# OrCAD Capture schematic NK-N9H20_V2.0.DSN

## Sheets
1 TOP: size A3; rev: 1.1; company: NuMaker-HMI-N9H20; note: TOP; note: NHS-55FA93 V1.0
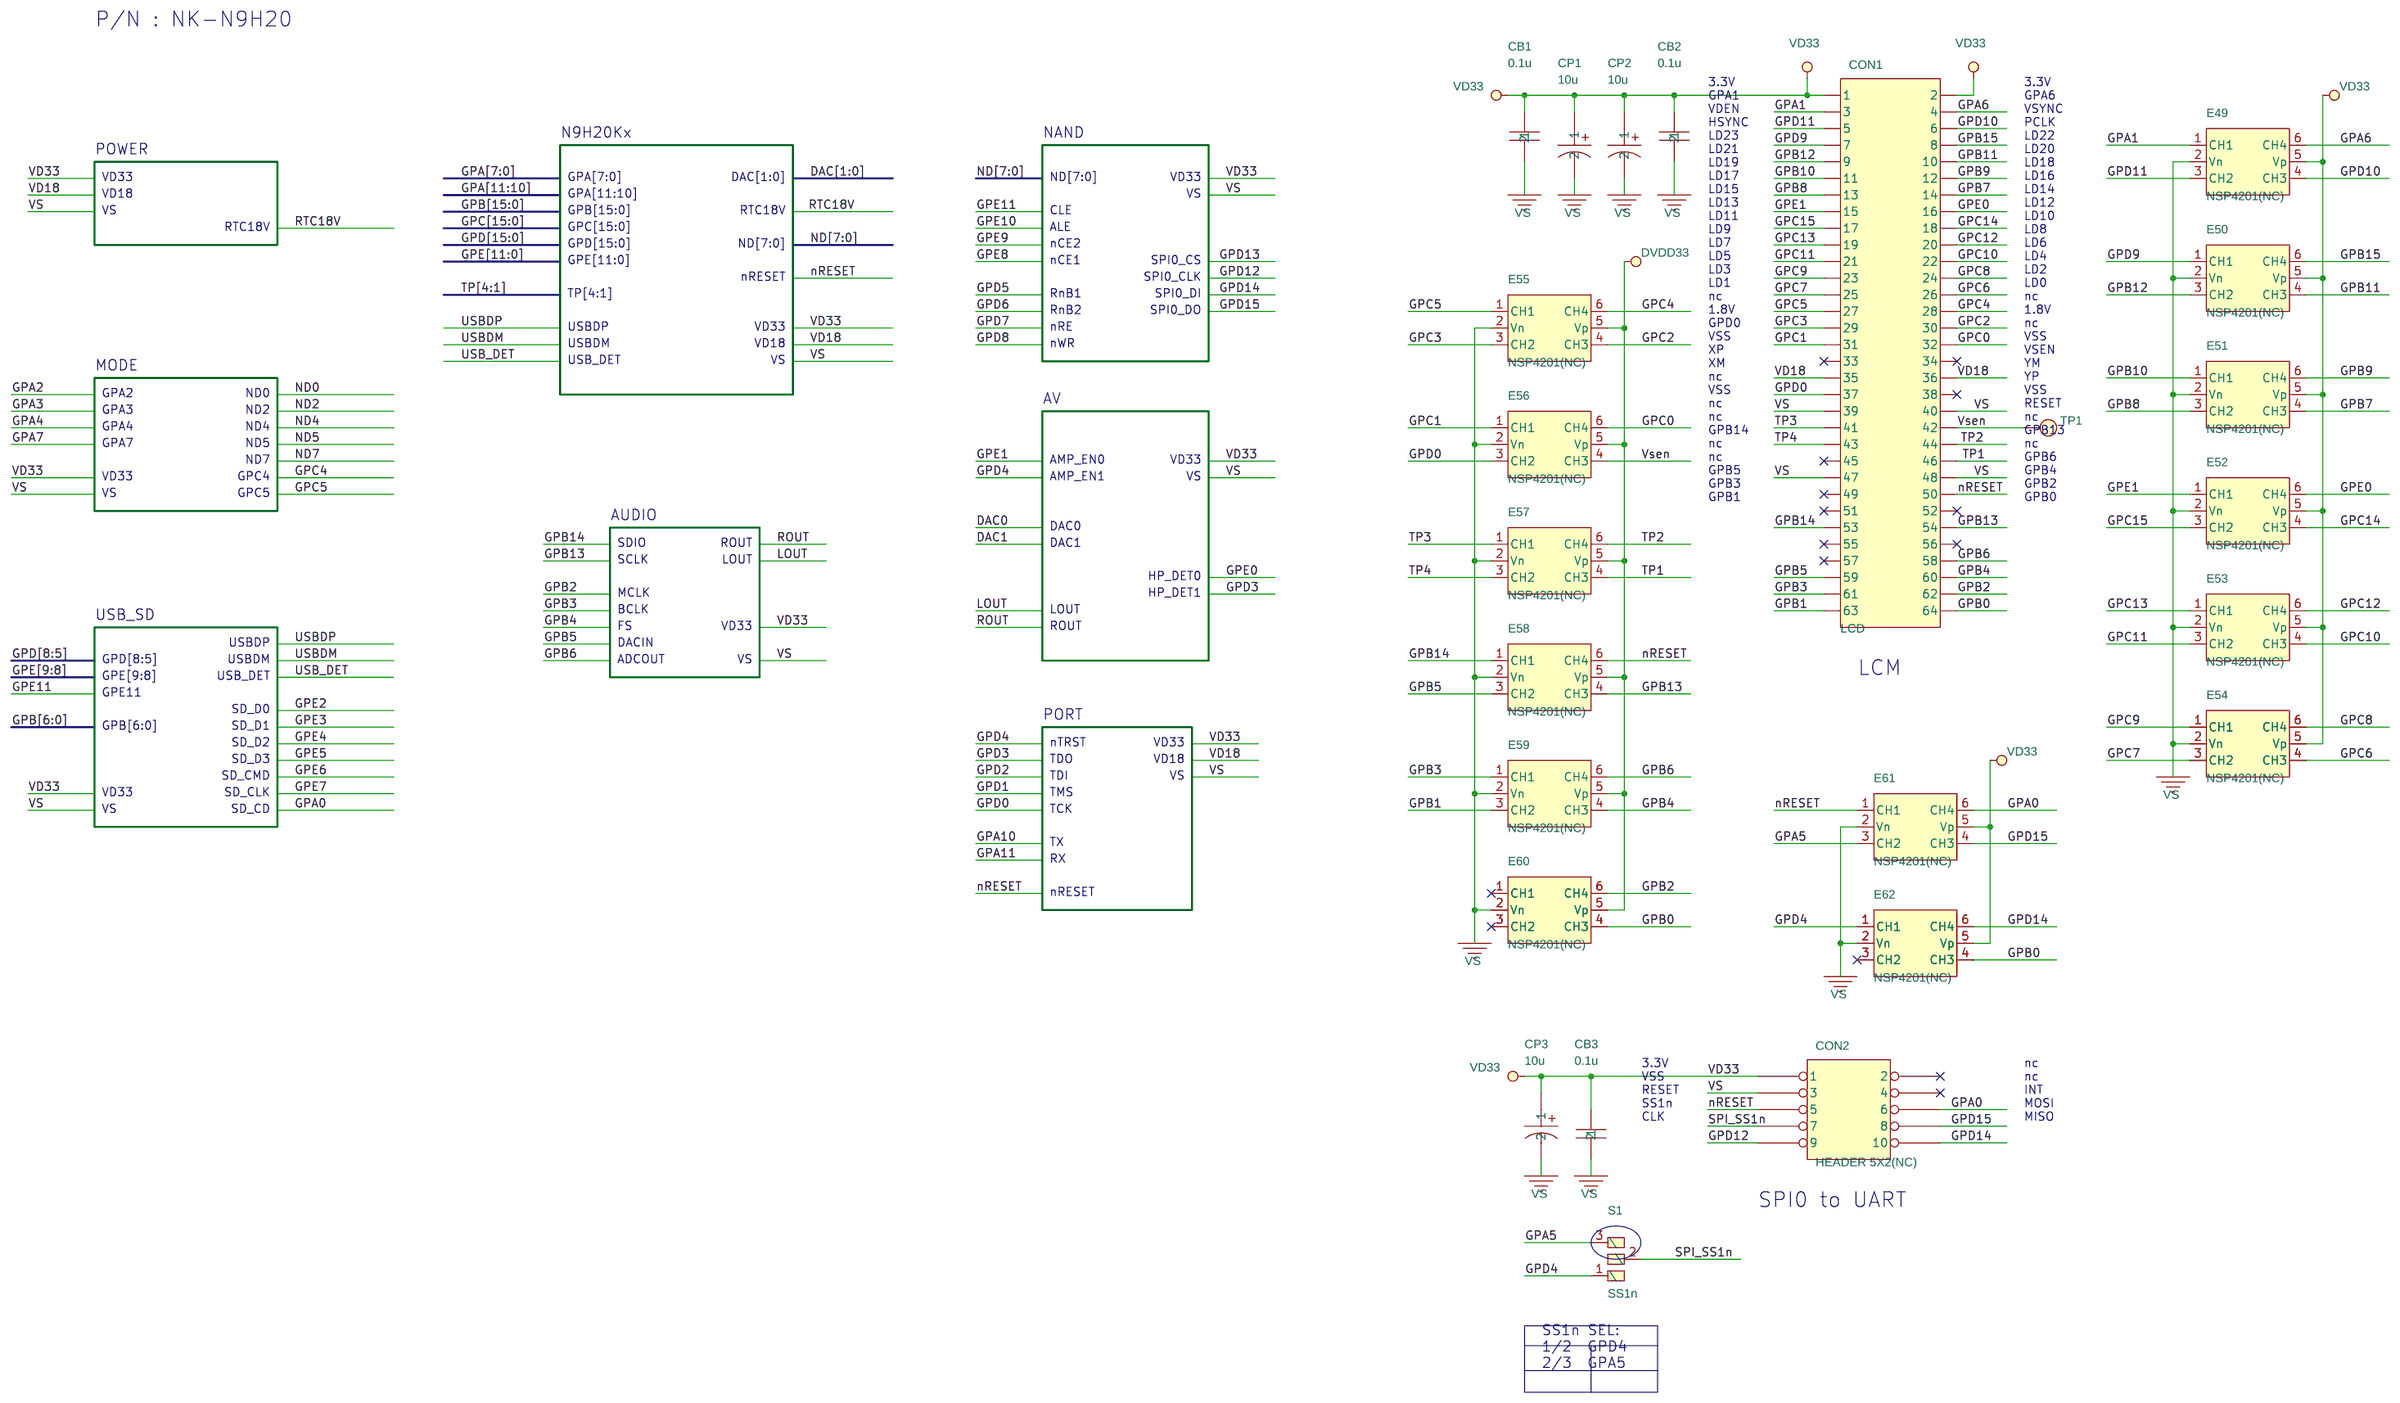
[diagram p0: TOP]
2 AV: size A4; note: AV; note: NuMaker-HMI-N9H20; block AV
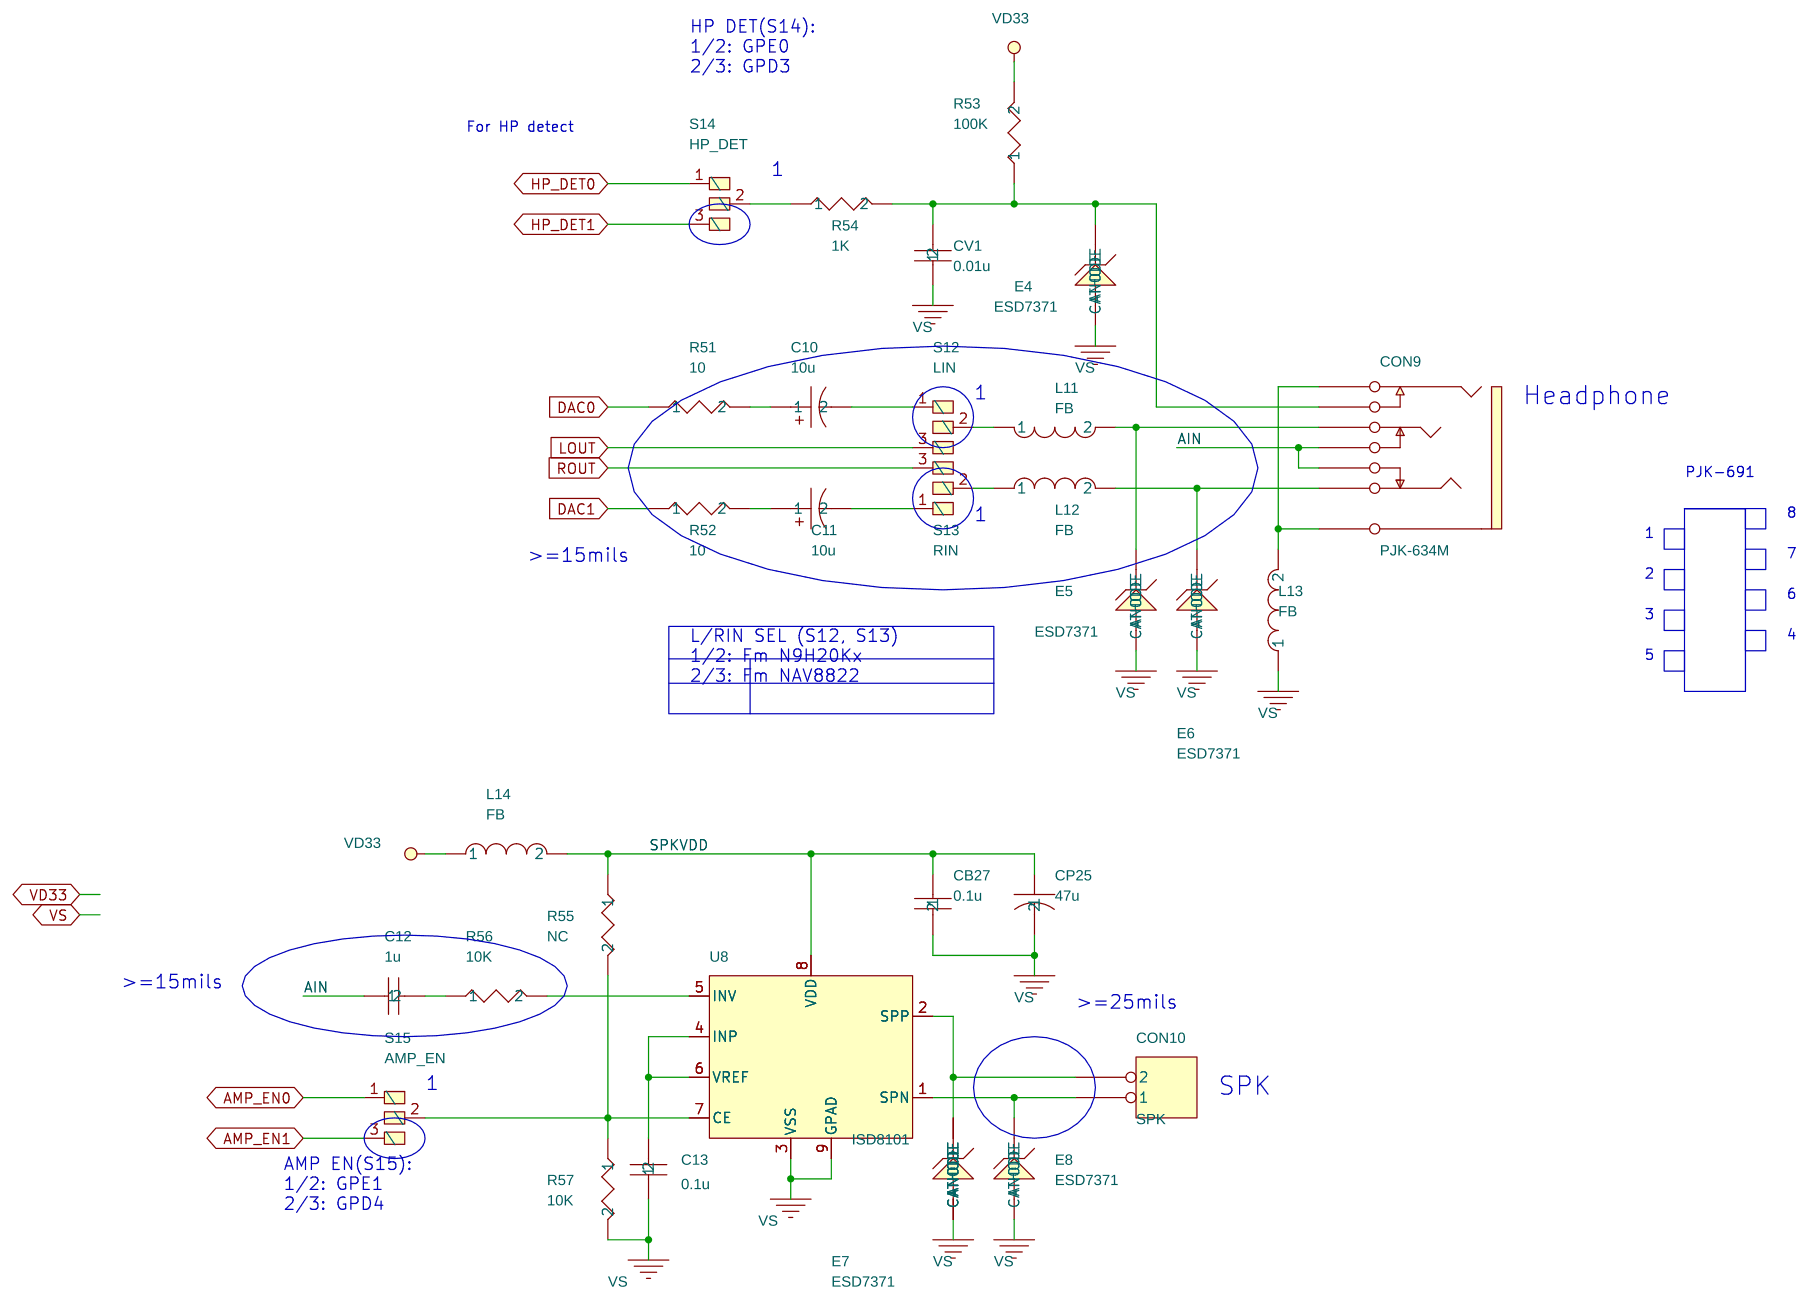
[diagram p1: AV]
3 USB_SD: size A4; note: USB_SD; block USB_SD
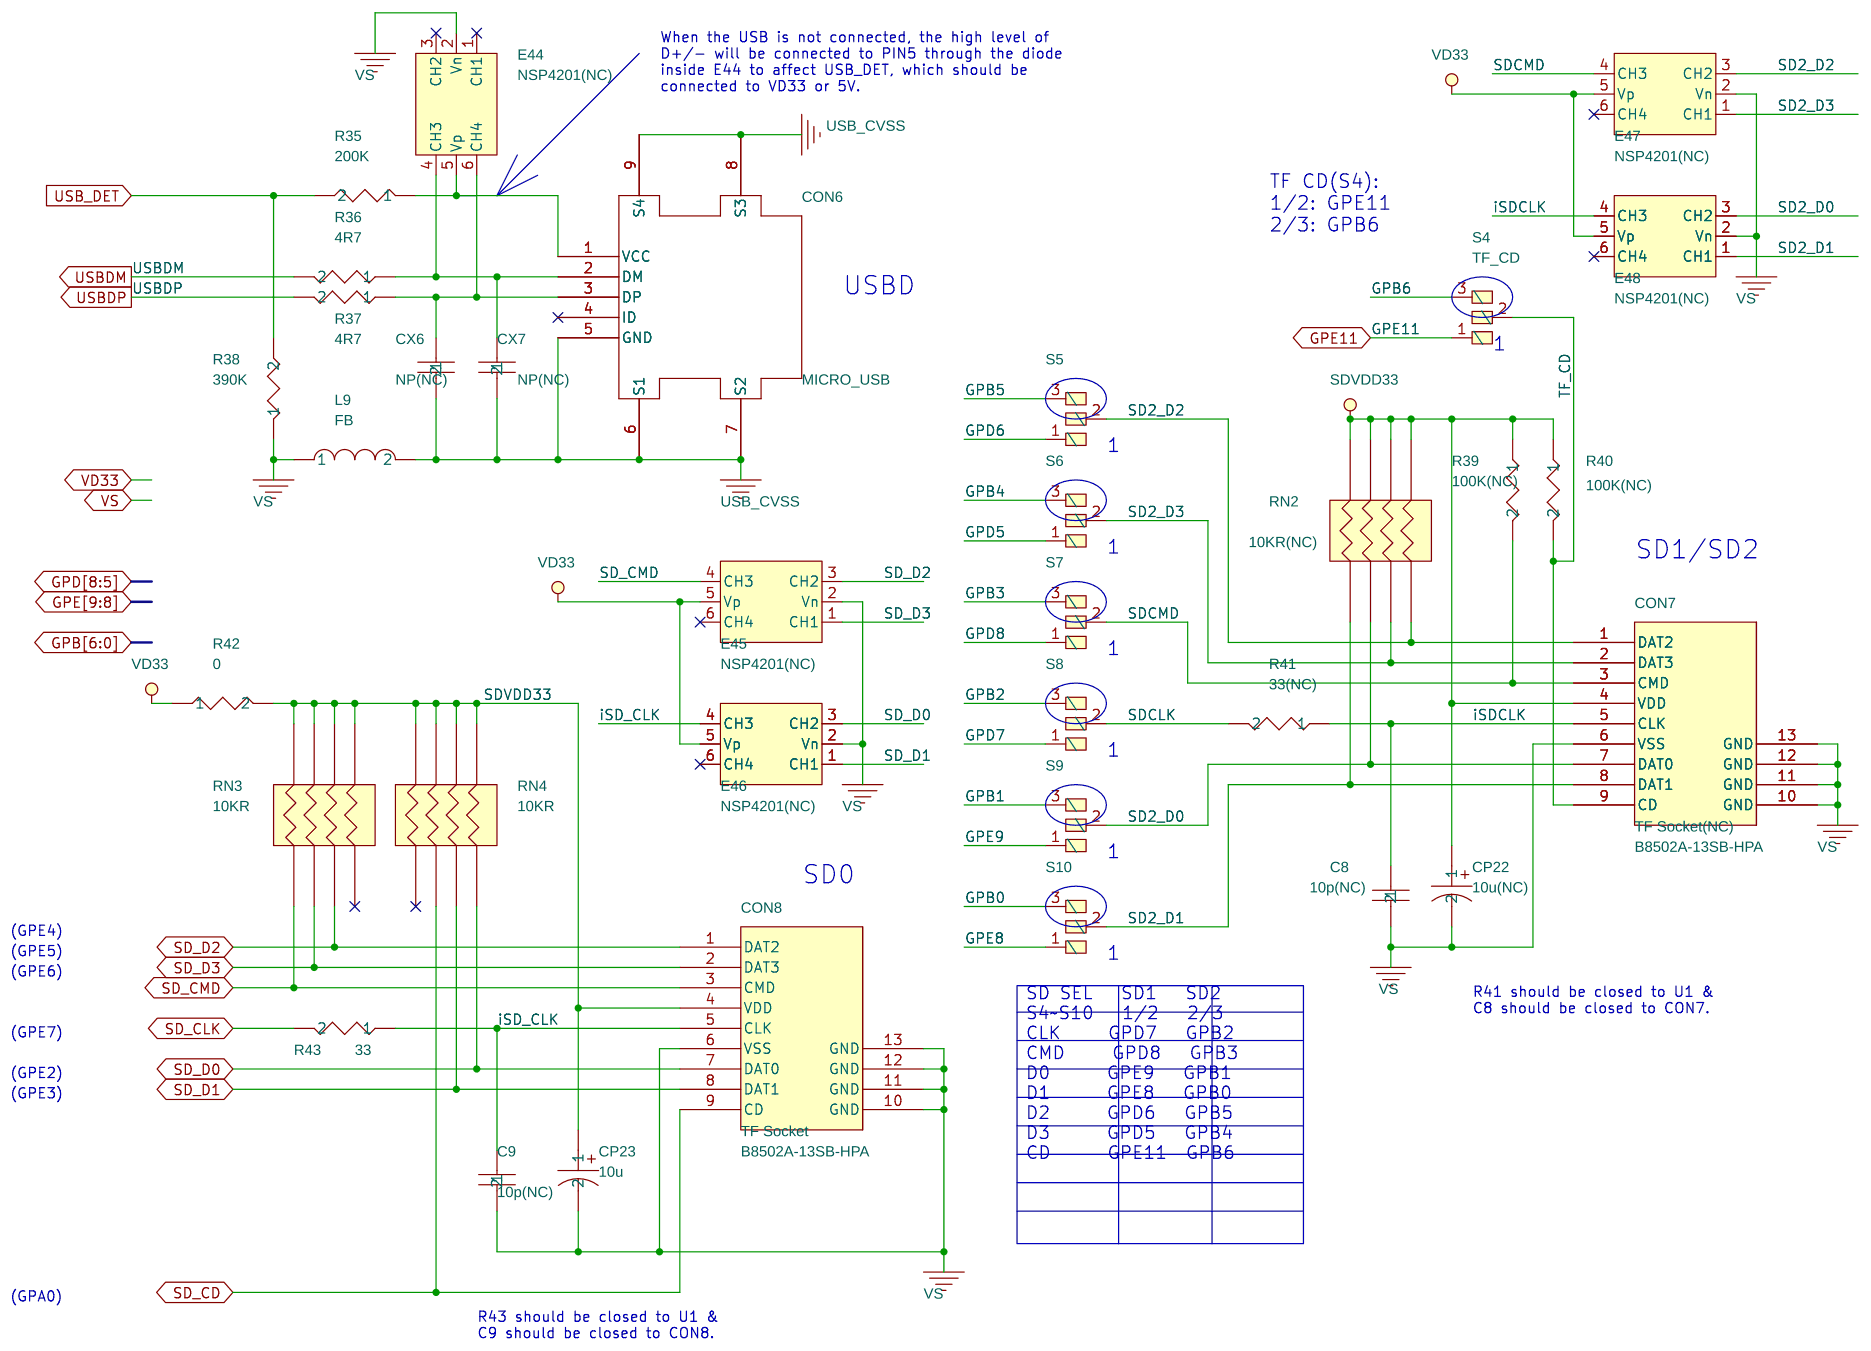
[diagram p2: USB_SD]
4 PORT: size A4; note: PORT; block PORT
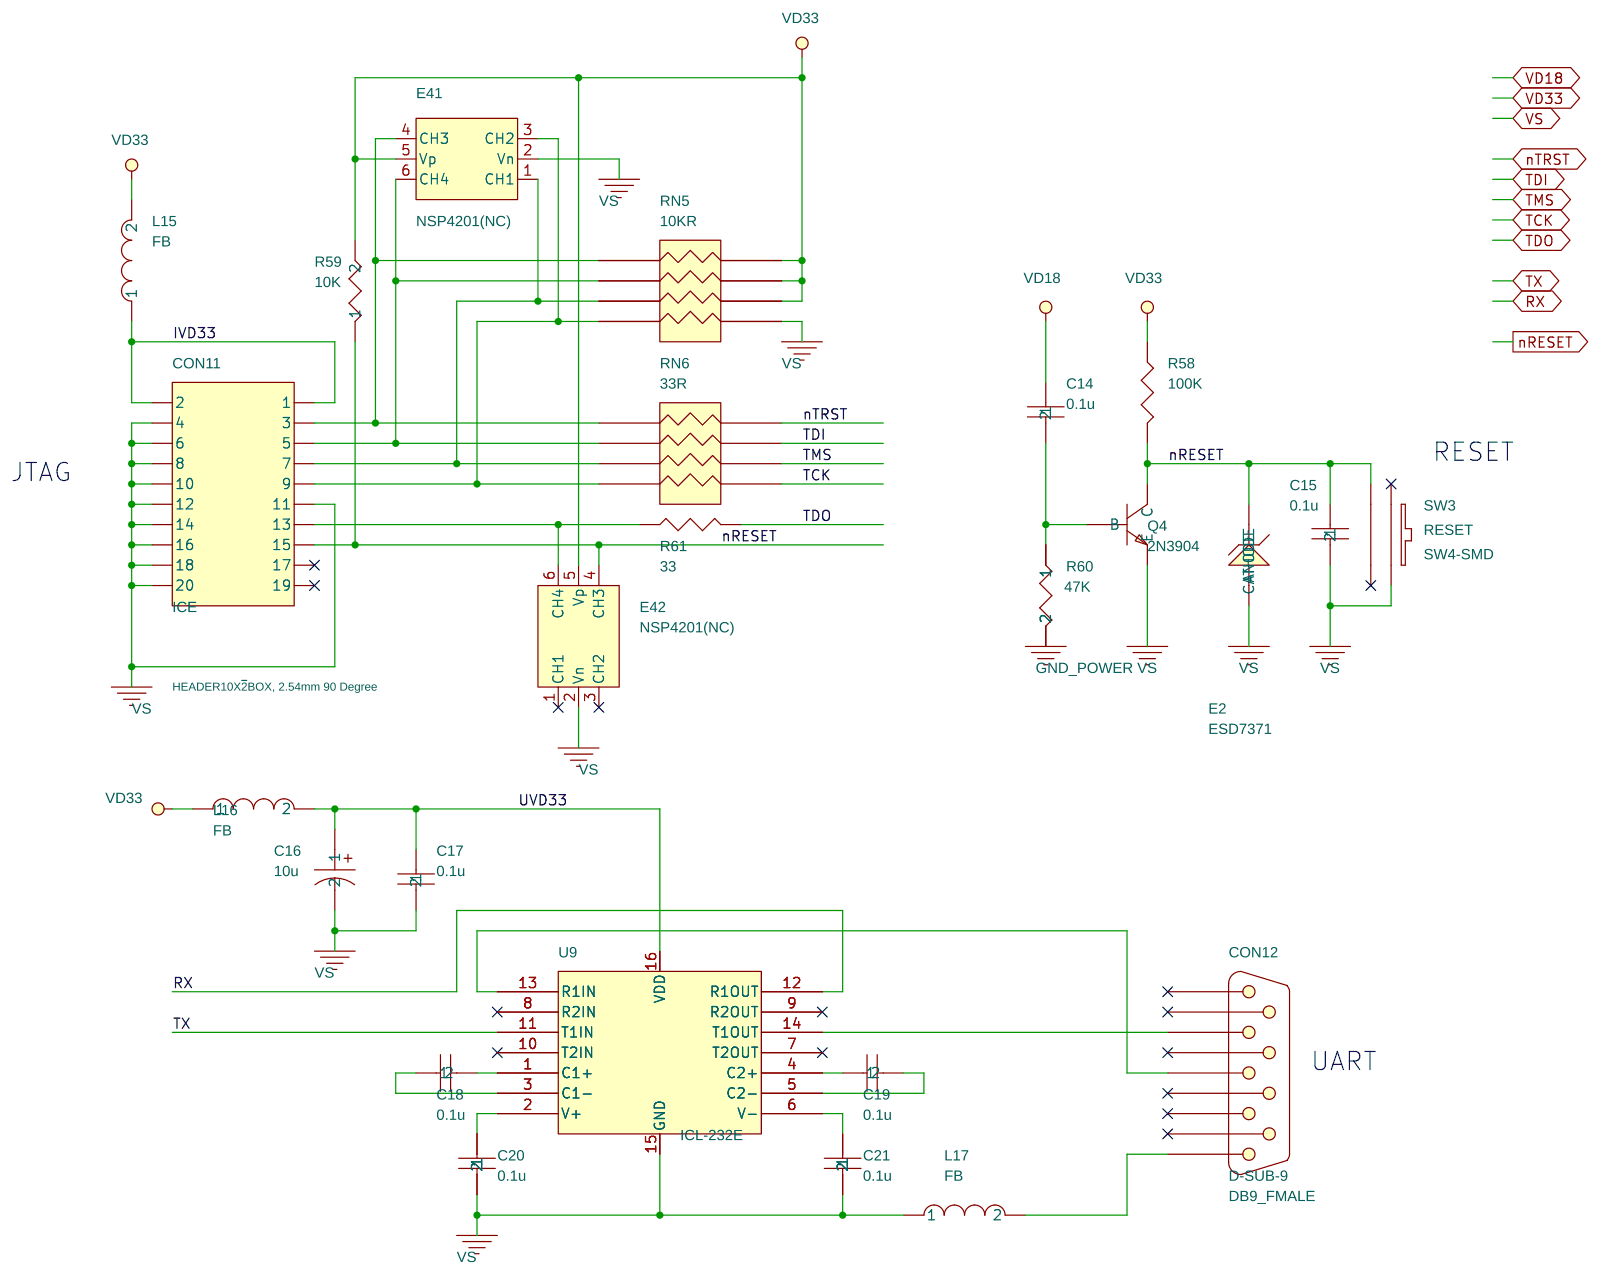
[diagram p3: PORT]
5 AUDIO: size A4; title: NuMaker-HMI-N9H20; note: AUDIO; block AUDIO
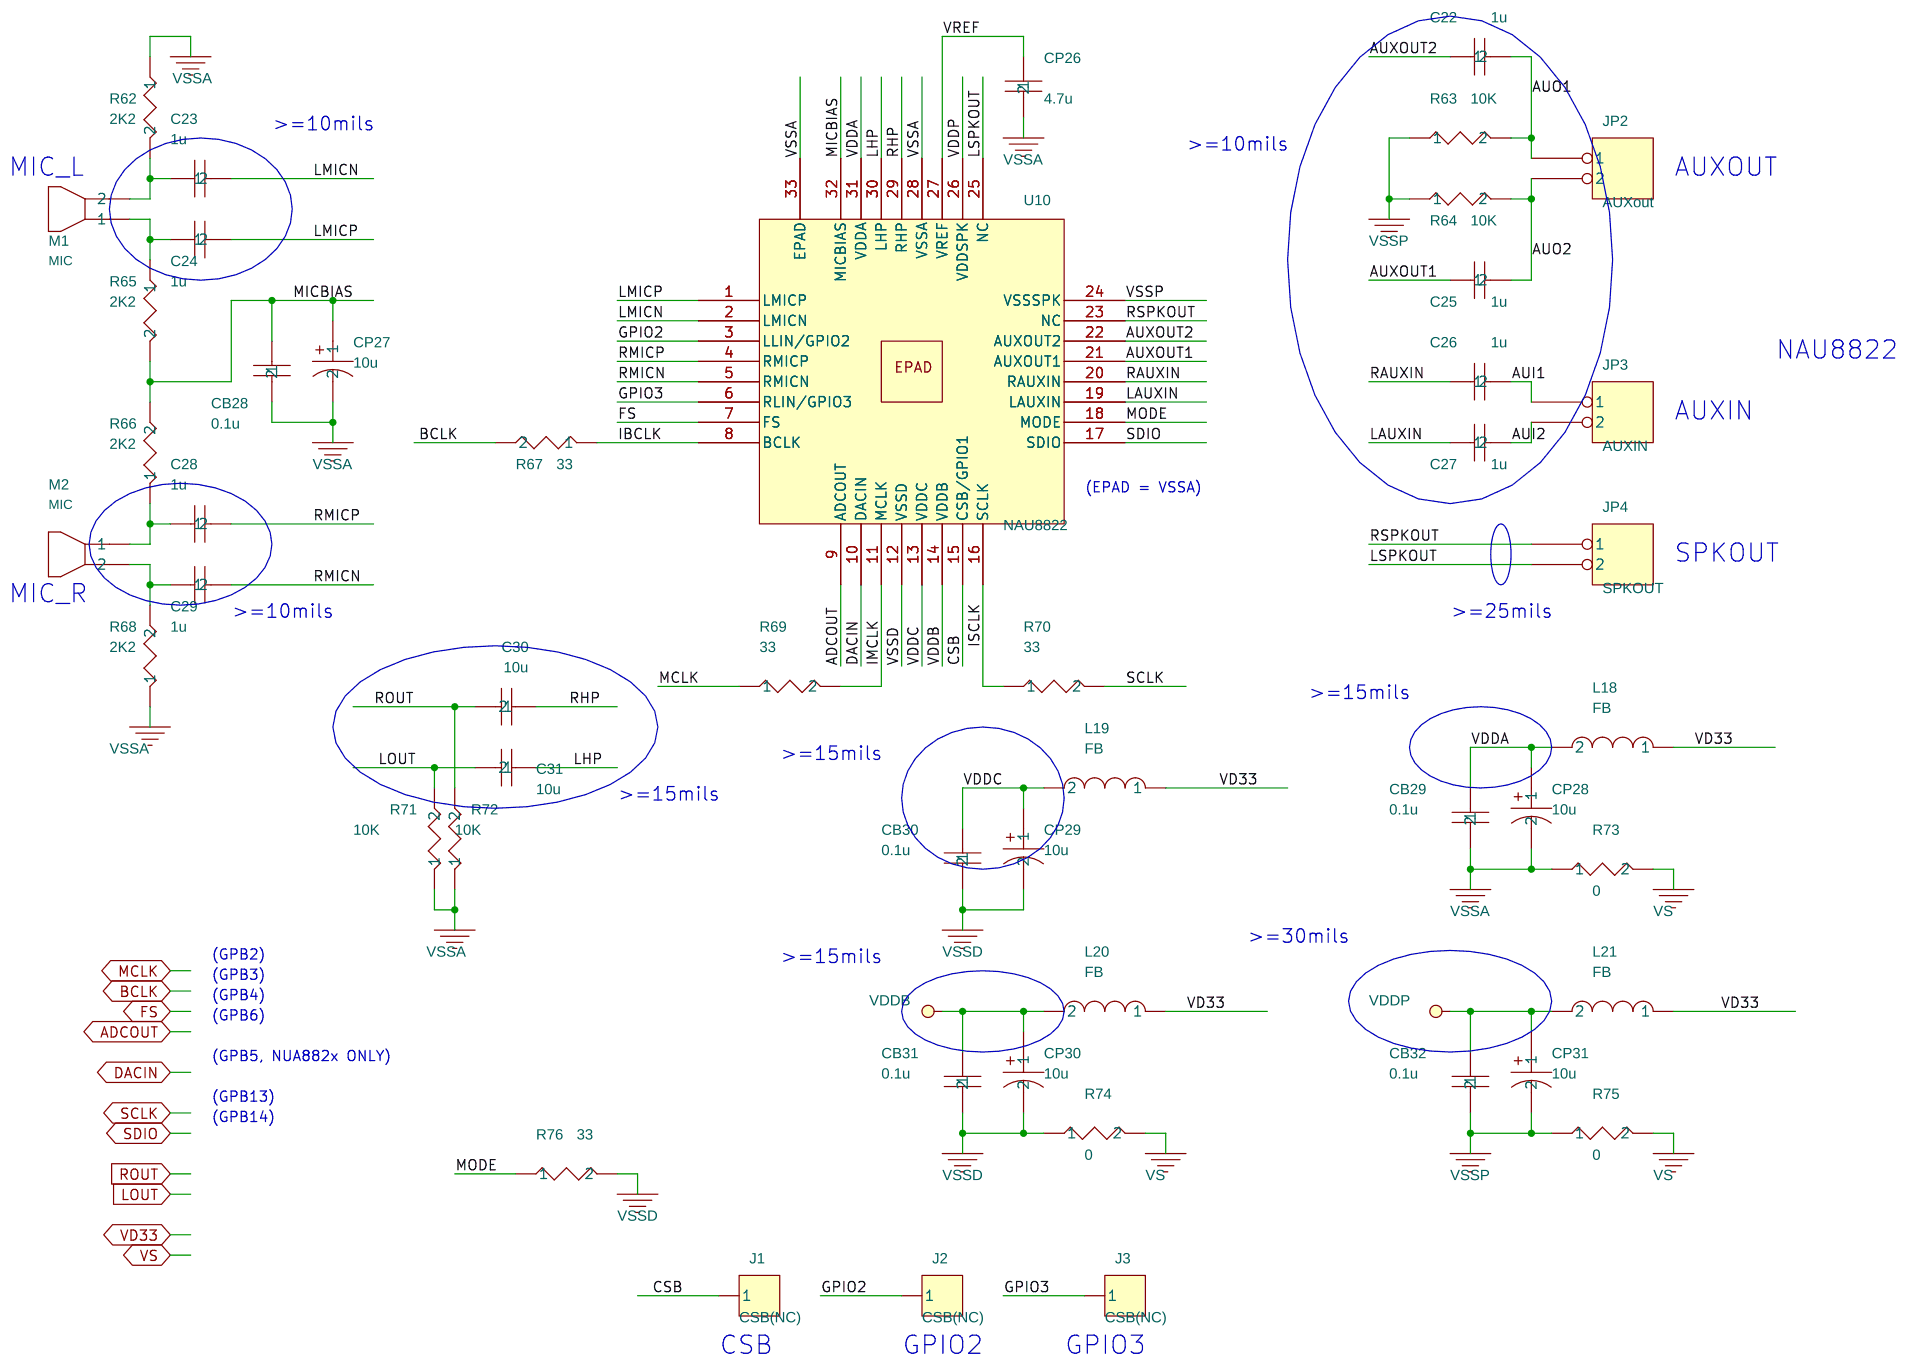
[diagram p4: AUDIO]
6 N9H20Kx: size A3; note: N9H20Kx Series; block N9H20Kx
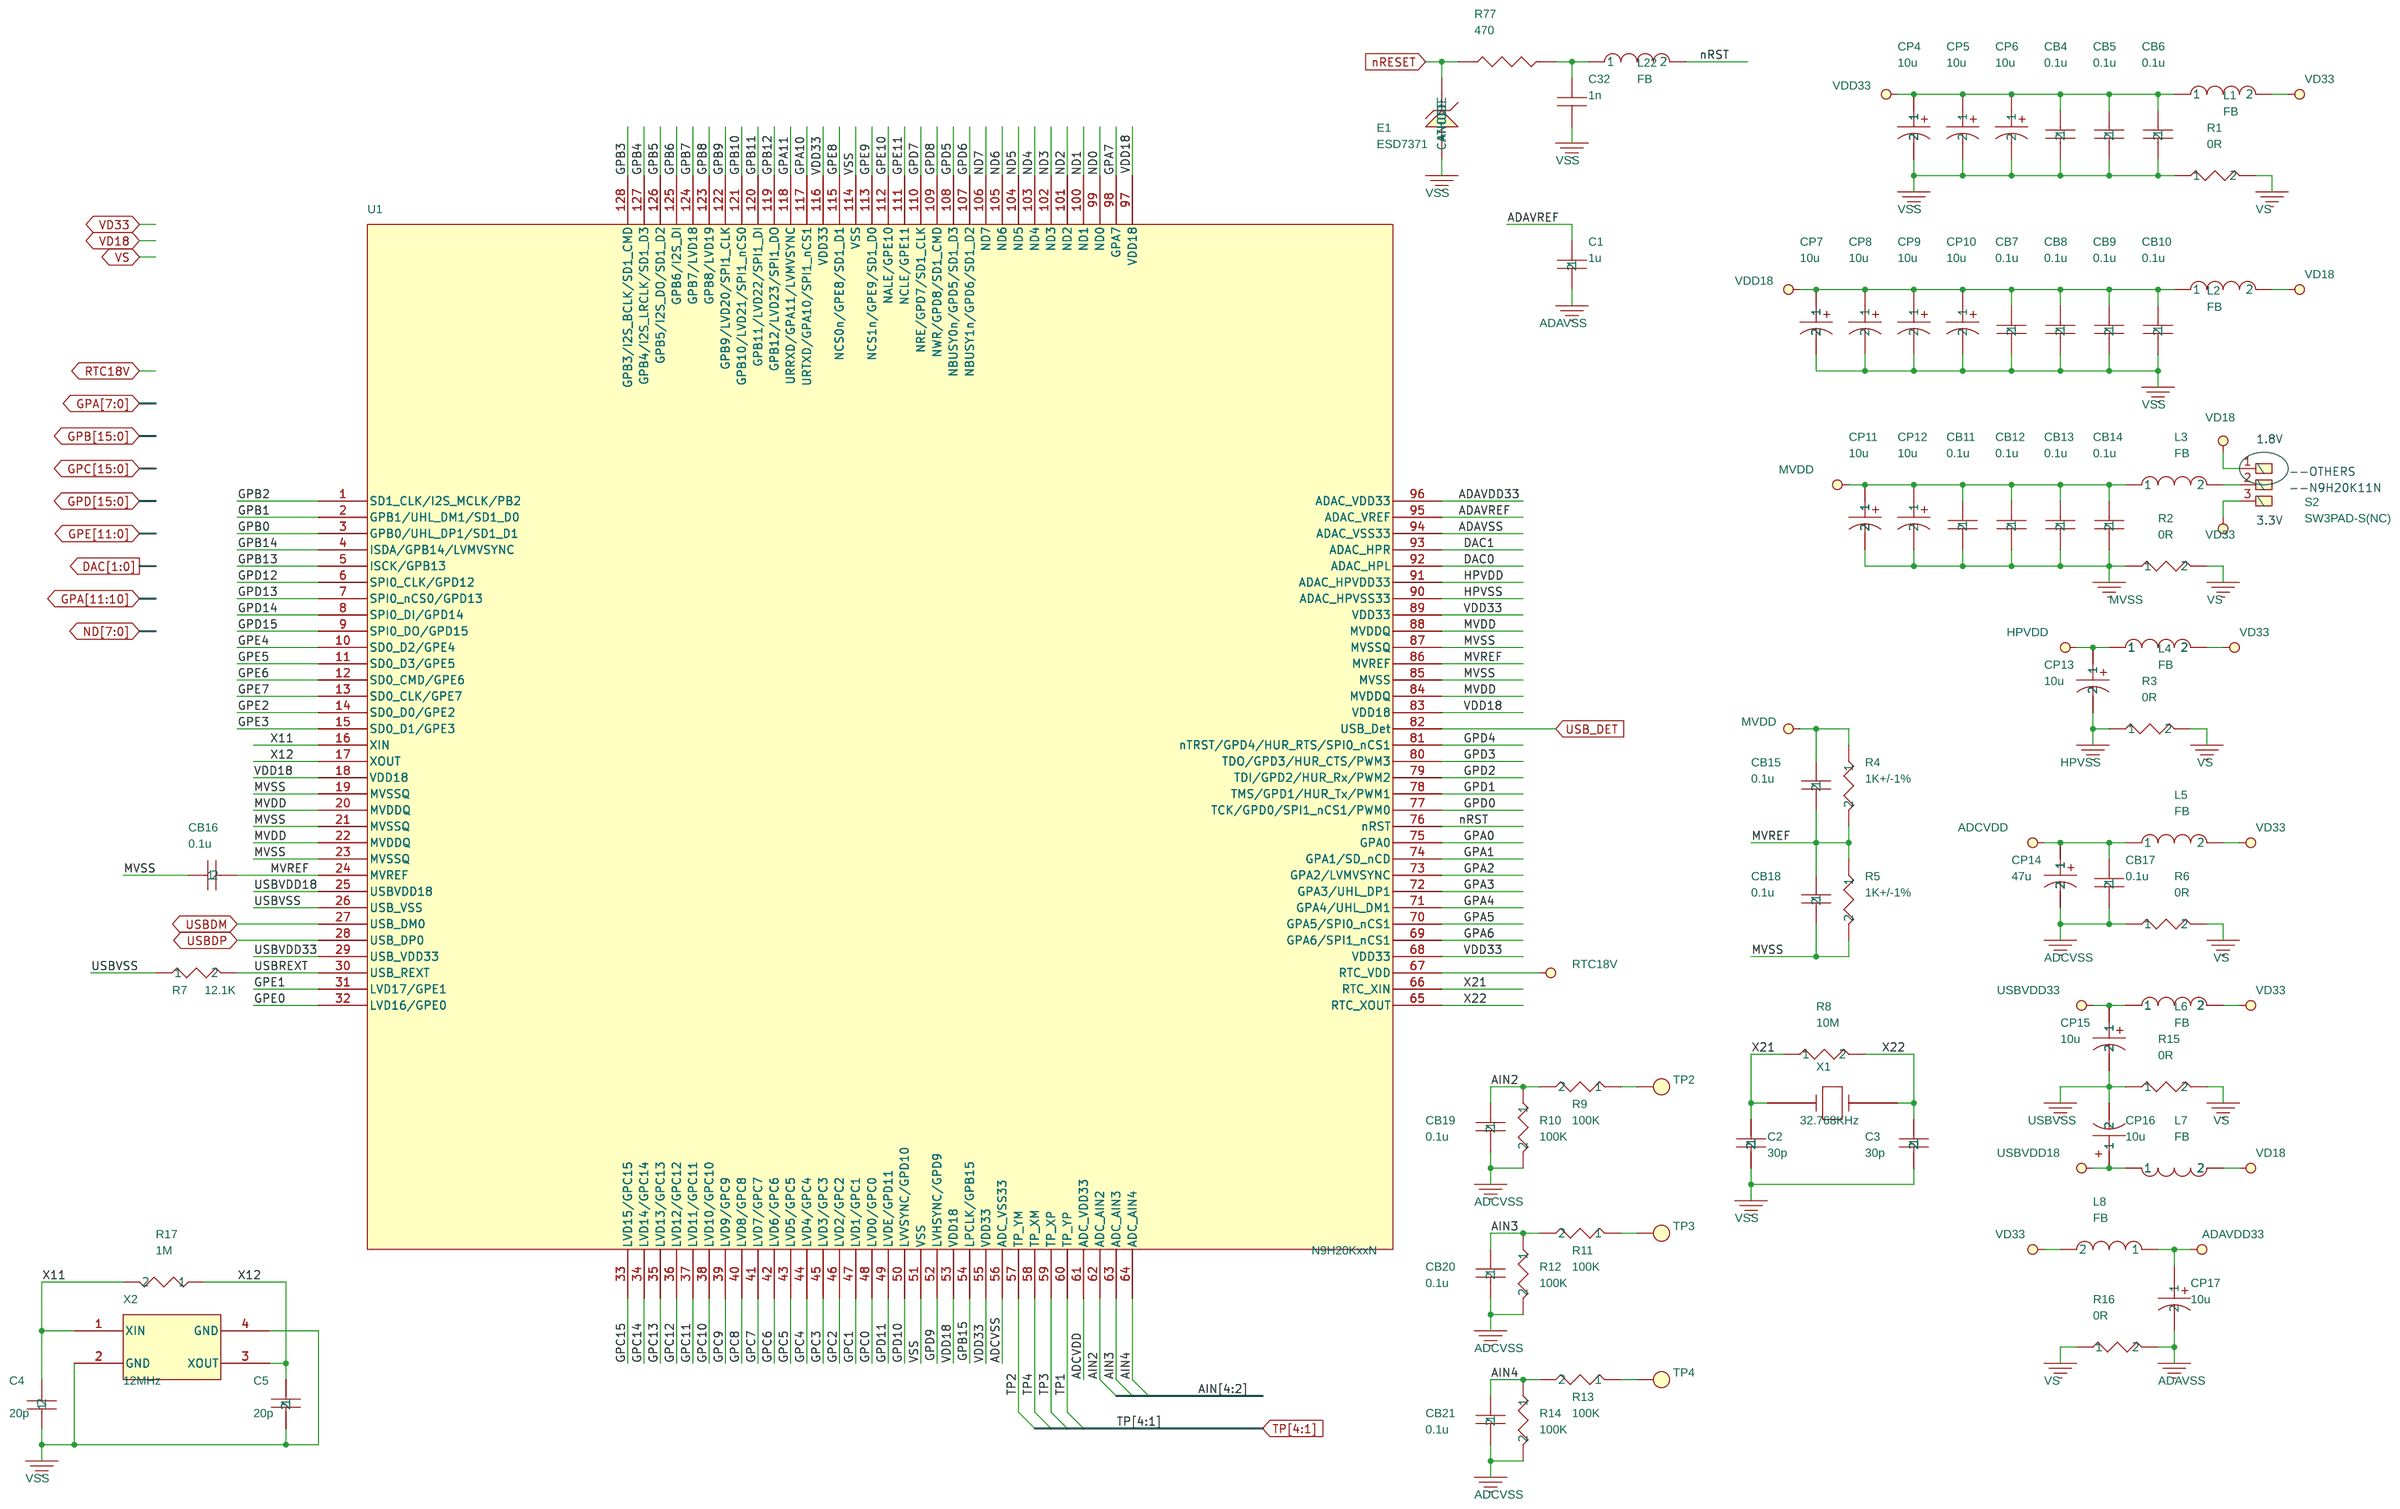
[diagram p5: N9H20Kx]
7 MODE: size A4; title: NuMaker-HMI-N9H20; note: MODE; block MODE
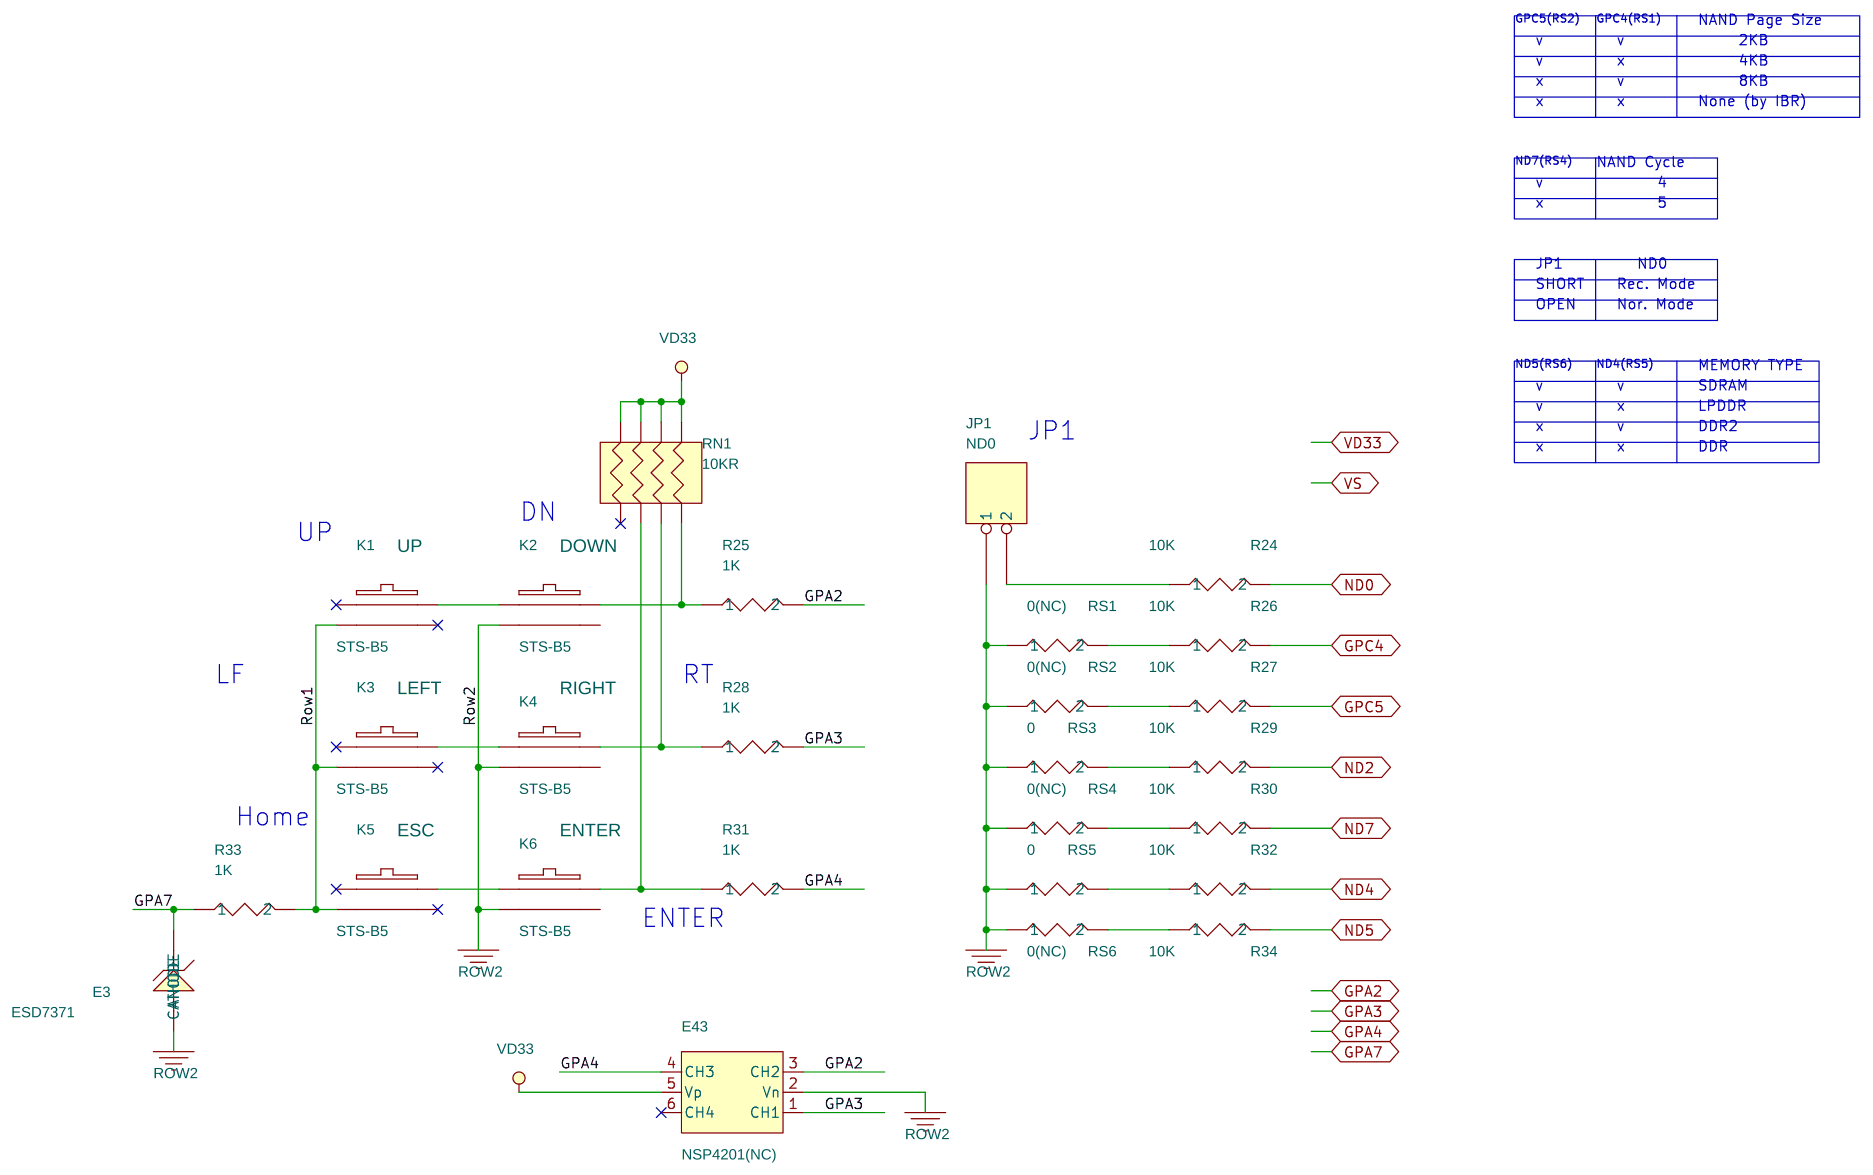
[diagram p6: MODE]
8 POWER: size A4; note: Power; block POWER
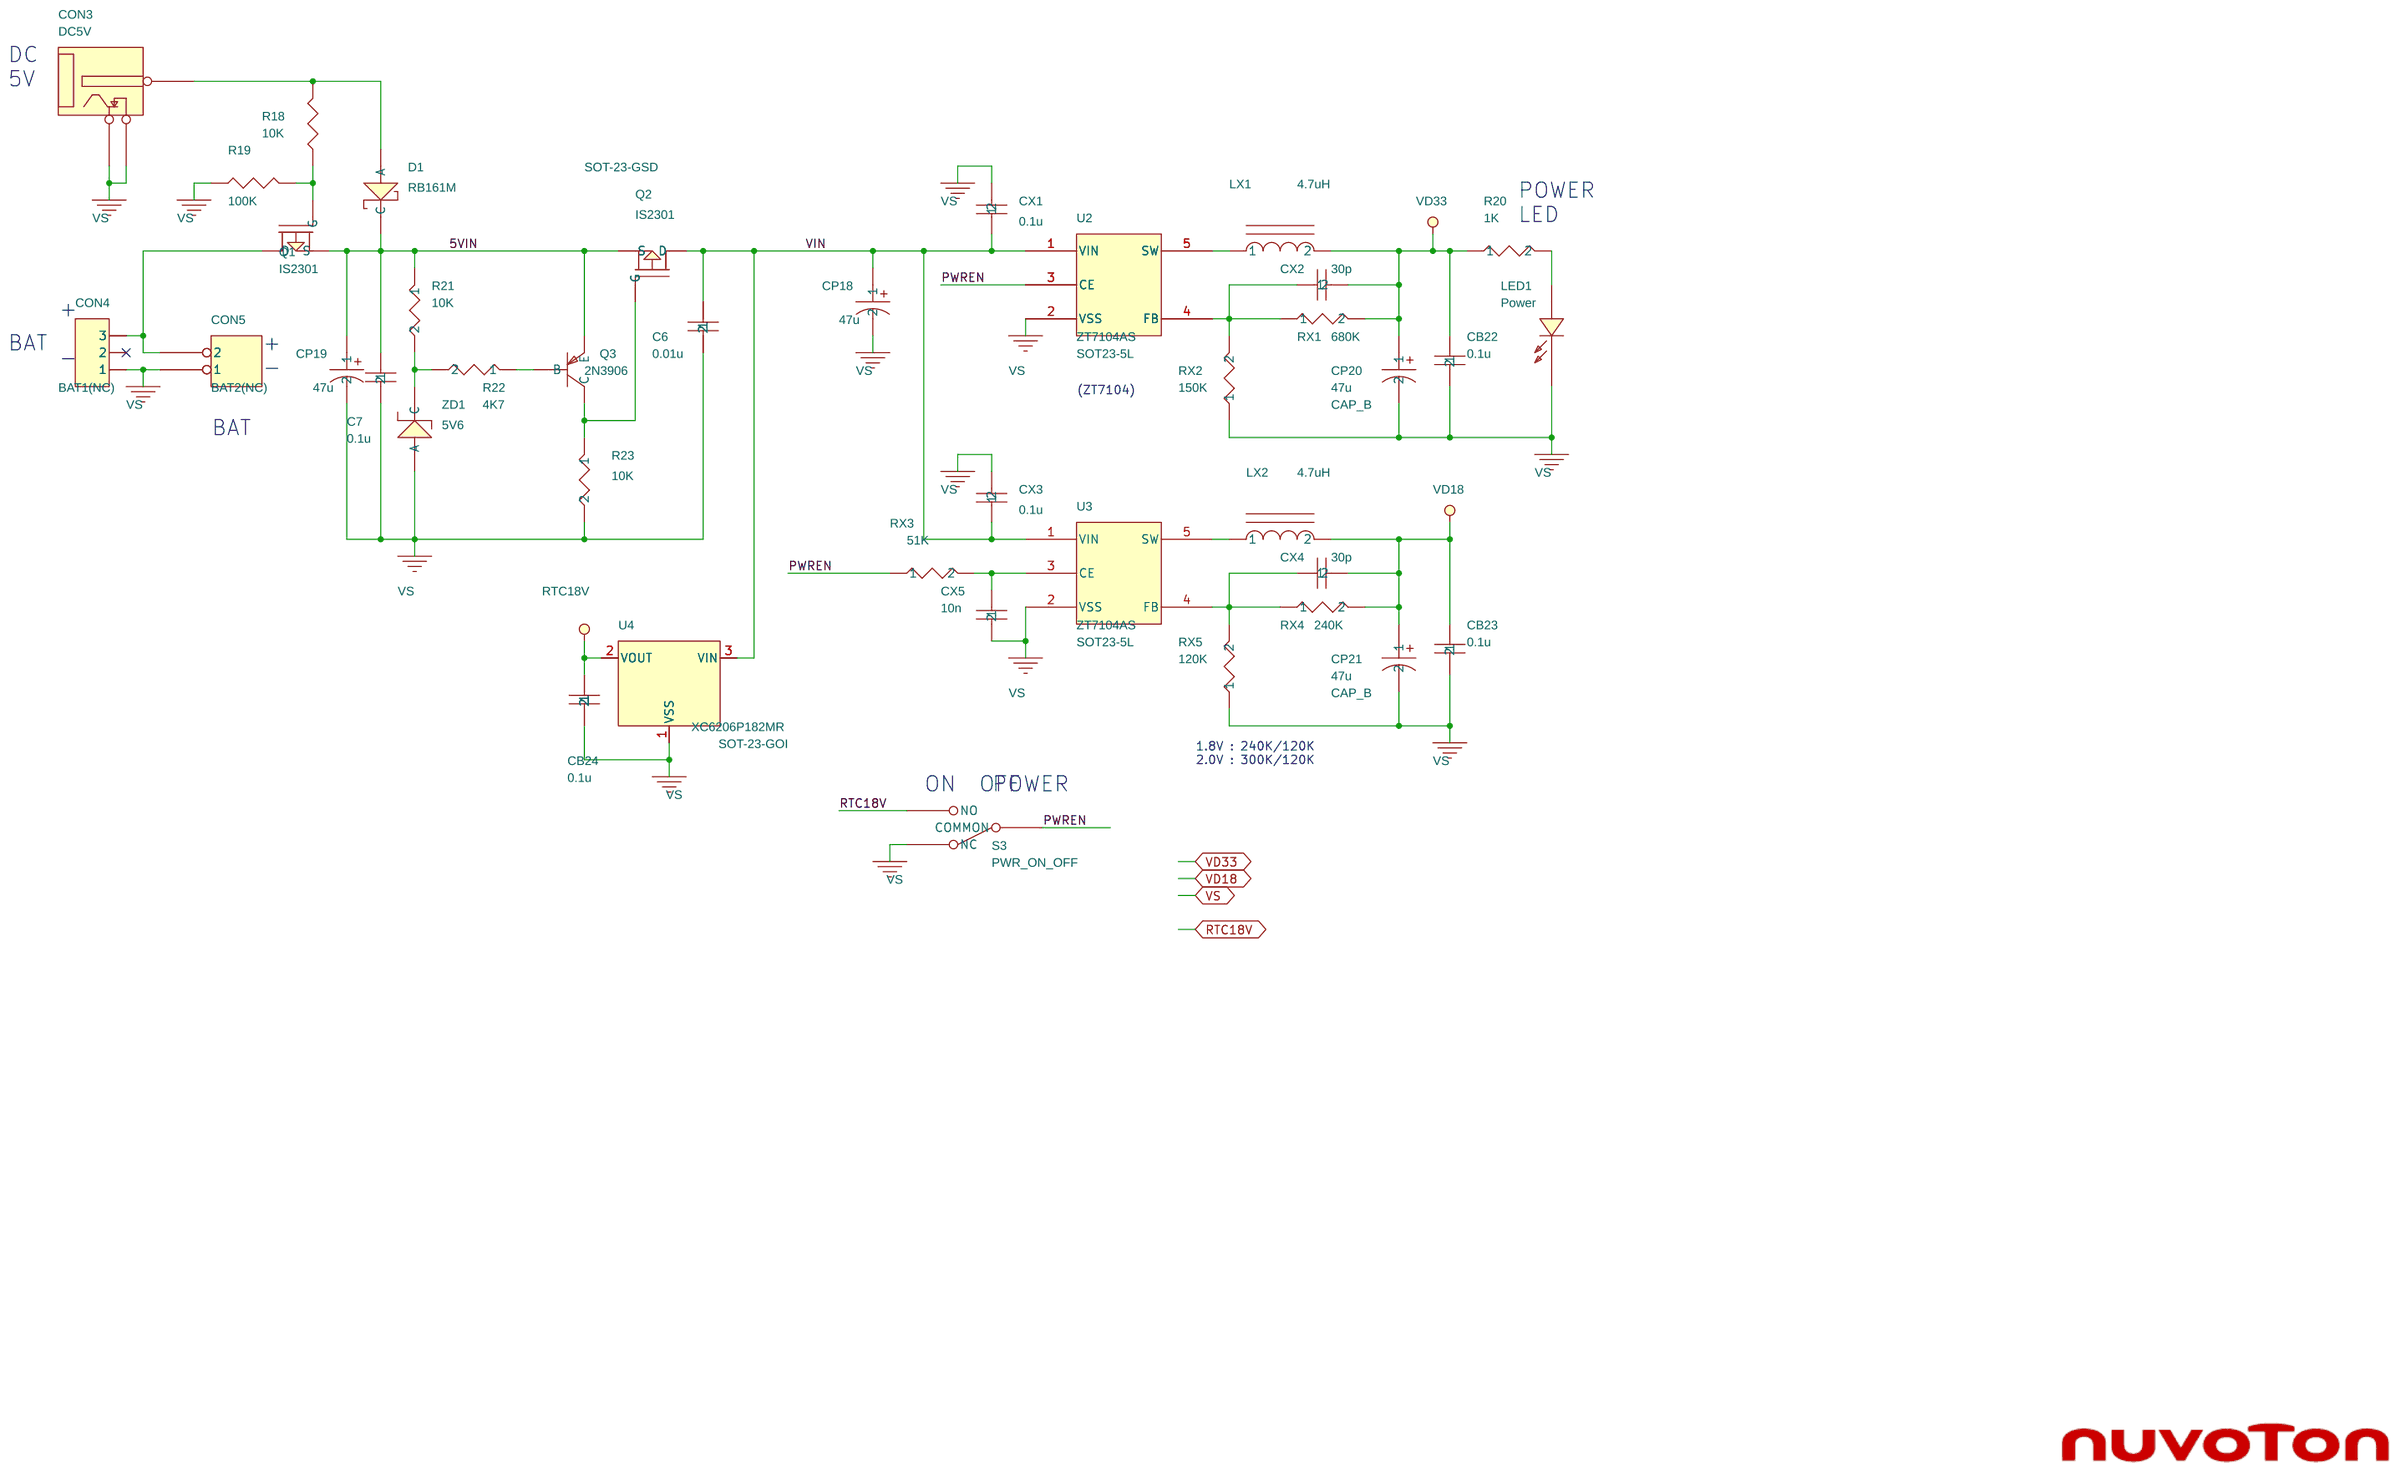
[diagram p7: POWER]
9 NAND: size A4; note: NAND; block NAND
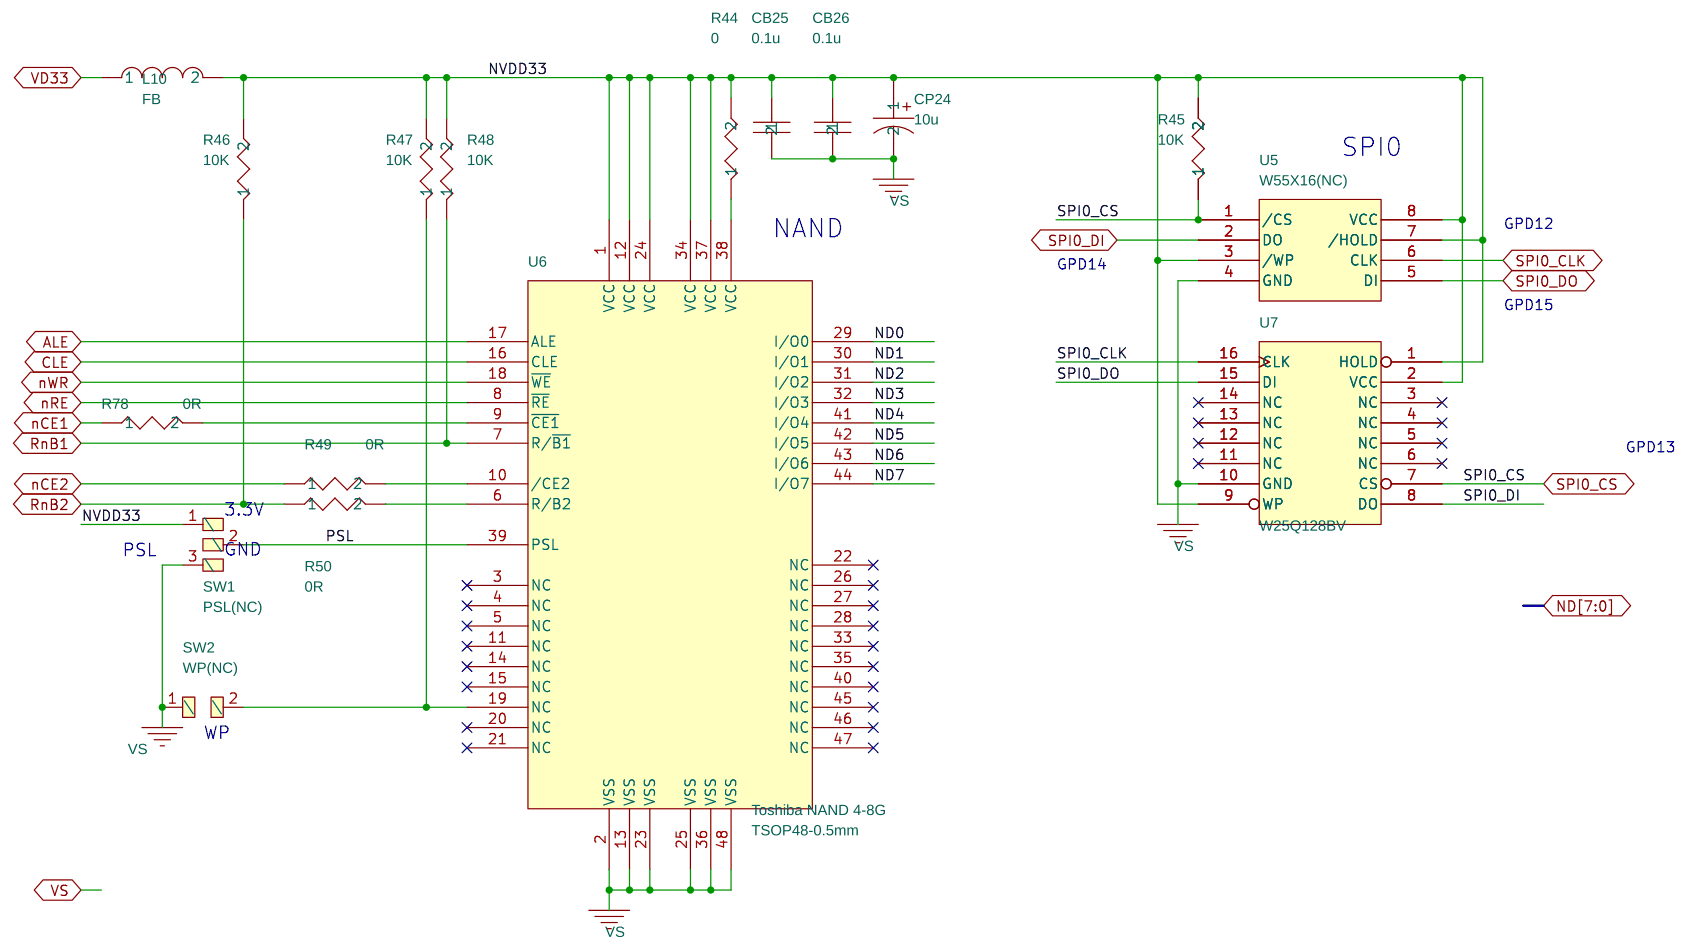
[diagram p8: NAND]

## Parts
sheet AUDIO
C22  1u  [C0603]
C23  1u  [C0603]
C24  1u  [C0603]
C25  1u  [C0603]
C26  1u  [C0603]
C27  1u  [C0603]
C28  1u  [C0603]
C29  1u  [C0603]
C30  10u  [C0603]
C31  10u  [C0603]
CB28  0.1u  [C0603]
CB29  0.1u  [C0603]
CB30  0.1u  [C0603]
CB31  0.1u  [C0603]
CB32  0.1u  [C0603]
CP26  4.7u  [C0603]
CP27  10u  [CAP_A]
CP28  10u  [CAP_A]
CP29  10u  [CAP_A]
CP30  10u  [CAP_A]
CP31  10u  [CAP_A]
J1  CSB(NC)  [1PAD_1.25X1.25MM]
J2  CSB(NC)  [1PAD_1.25X1.25MM]
J3  CSB(NC)  [1PAD_1.25X1.25MM]
JP2  AUXout  [Header22.54MM]
JP3  AUXIN  [Header22.54MM]
JP4  SPKOUT  [Header22.54MM]
L18  FB  [L0603]
L19  FB  [L0603]
L20  FB  [L0603]
L21  FB  [L0603]
M1  MIC  [LF-M6027]
M2  MIC  [LF-M6027]
R62  2K2  [R0603]
R63  10K  [R0603]
R64  10K  [R0603]
R65  2K2  [R0603]
R66  2K2  [R0603]
R67  33  [R0603]
R68  2K2  [R0603]
R69  33  [R0603]
R70  33  [R0603]
R71  10K  [R0603]
R72  10K  [R0603]
R73  0  [R0603]
R74  0  [R0603]
R75  0  [R0603]
R76  33  [R0603]
U10  NAU8822  [QFN32L_5MMX5MM0.5MMLEADPITCH]
sheet AV
C10  10u  [CAP_A]
C11  10u  [CAP_A]
C12  1u  [C0603]
C13  0.1u  [C0603]
CB27  0.1u  [C0603]
CON9  PJK-634M  [PJK-634M]
CON10  SPK  [HEADER22.54MM]
CP25  47u  [CAP_B]
CV1  0.01u  [C0603]
E4  ESD7371  [SOD-523]
E5  ESD7371  [SOD-523]
E6  ESD7371  [SOD-523]
E7  ESD7371  [SOD-523]
E8  ESD7371  [SOD-523]
L11  FB  [L0603]
L12  FB  [L0603]
L13  FB  [L0603]
L14  FB  [L0603]
R51  10  [R0603]
R52  10  [R0603]
R53  100K  [R0603]
R54  1K  [R0603]
R55  NC  [R0603]
R56  10K  [R0603]
R57  10K  [R0603]
S12  LIN  [3P-1.2mm]
S13  RIN  [3P-1.2mm]
S14  HP_DET  [3P-1.2mm]
S15  AMP_EN  [3P-1.2mm]
U8  ISD8101  [SOP-8_E]
sheet MODE
E3  ESD7371  [SOD-523]
E43  NSP4201(NC)  [TSOP-6]
JP1  ND0  [Header22.0MM]
K1  UP  [STS-B5]
K2  DOWN  [STS-B5]
K3  LEFT  [STS-B5]
K4  RIGHT  [STS-B5]
K5  ESC  [STS-B5]
K6  ENTER  [STS-B5]
R24  10K  [R0603]
R25  1K  [R0603]
R26  10K  [R0603]
R27  10K  [R0603]
R28  1K  [R0603]
R29  10K  [R0603]
R30  10K  [R0603]
R31  1K  [R0603]
R32  10K  [R0603]
R33  1K  [R0603]
R34  10K  [R0603]
RN1  10KR  [8P4R_0603]
RS1  0(NC)  [R0603]
RS2  0(NC)  [R0603]
RS3  0  [R0603]
RS4  0(NC)  [R0603]
RS5  0  [R0603]
RS6  0(NC)  [R0603]
sheet N9H20Kx
C1  1u  [C0603]
C2  30p  [C0603]
C3  30p  [C0603]
C4  20p  [C0603]
C5  20p  [C0603]
C32  1n  [0603C]
CB4  0.1u  [C0603]
CB5  0.1u  [C0603]
CB6  0.1u  [C0603]
CB7  0.1u  [C0603]
CB8  0.1u  [C0603]
CB9  0.1u  [C0603]
CB10  0.1u  [C0603]
CB11  0.1u  [C0603]
CB12  0.1u  [C0603]
CB13  0.1u  [C0603]
CB14  0.1u  [C0603]
CB15  0.1u  [C0603]
CB16  0.1u  [C0603]
CB17  0.1u  [C0603]
CB18  0.1u  [C0603]
CB19  0.1u  [C0603]
CB20  0.1u  [C0603]
CB21  0.1u  [C0603]
CP4  10u  [CAP_A]
CP5  10u  [CAP_A]
CP6  10u  [CAP_A]
CP7  10u  [CAP_A]
CP8  10u  [CAP_A]
CP9  10u  [CAP_A]
CP10  10u  [CAP_A]
CP11  10u  [CAP_A]
CP12  10u  [CAP_A]
CP13  10u  [CAP_A]
CP14  47u  [CAP_B]
CP15  10u  [CAP_A]
CP16  10u  [CAP_A]
CP17  10u  [CAP_A]
E1  ESD7371  [SOD-523]
L1  FB  [L0603]
L2  FB  [L0603]
L3  FB  [L0603]
L4  FB  [L0603]
L5  FB  [L0603]
L6  FB  [L0603]
L7  FB  [L0603]
L8  FB  [L0603]
L22  FB  [L0603]
R1  0R  [R0603]
R2  0R  [R0603]
R3  0R  [R0603]
R4  1K+/-1%  [R0603]
R5  1K+/-1%  [R0603]
R6  0R  [R0603]
R7  12.1K  [R0603]
R8  10M  [R0603]
R9  100K  [R0603]
R10  100K  [R0603]
R11  100K  [R0603]
R12  100K  [R0603]
R13  100K  [R0603]
R14  100K  [R0603]
R15  0R  [R0603]
R16  0R  [R0603]
R17  1M  [R0603]
R77  470  [0603R]
S2  SW3PAD-S(NC)  [3P-1.2mm]
TP2  T POINT R  [1PAD_1.25X1.25MM]
TP3  T POINT R  [1PAD_1.25X1.25MM]
TP4  T POINT R  [1PAD_1.25X1.25MM]
U1  N9H20KxxN  [LQFP-12814X14MMFOOTPRINT2.0MM]
X1  32.768KHz  [9HT9]
X2  12MHz  [XRGBBCNANF-27M]
sheet NAND
CB25  0.1u  [C0603]
CB26  0.1u  [C0603]
CP24  10u  [CAP_A]
L10  FB  [L0603]
R44  0  [R0603]
R45  10K  [R0603]
R46  10K  [R0603]
R47  10K  [R0603]
R48  10K  [R0603]
R49  0R  [R0603]
R50  0R  [R0603]
R78  0R  [R0603]
SW1  PSL(NC)  [3P-1.2mm]
SW2  WP(NC)  [2P-1.2mm]
U5  W55X16(NC)  [SOIC8_208]
U6  Toshiba NAND 4-8G  [TSOP48-0.5mm]
U7  W25Q128BV  [SOIC16_300]
sheet PORT
C14  0.1u  [C0603]
C15  0.1u  [C0603]
C16  10u  [CAP_A]
C17  0.1u  [C0603]
C18  0.1u  [C0603]
C19  0.1u  [C0603]
C20  0.1u  [C0603]
C21  0.1u  [C0603]
CON11  ICE  [HEADER10X2\BOX, 2.54mm 90 Degree]
CON12  D-SUB-9  [DB9_FMALE]
E2  ESD7371  [SOD-523]
E41  NSP4201(NC)  [TSOP-6]
E42  NSP4201(NC)  [TSOP-6]
L15  FB  [L0603]
L16  FB  [L0603]
L17  FB  [L0603]
Q4  2N3904  [SOT23-BEC]
R58  100K  [R0603]
R59  10K  [R0603]
R60  47K  [R0603]
R61  33  [R0603]
RN5  10KR  [8P4R_0603]
RN6  33R  [8P4R_0603]
SW3  RESET  [SW4-SMD]
U9  ICL-232E  [NSOIC-16L]
sheet POWER
C6  0.01u  [C0603]
C7  0.1u  [C0603]
CB22  0.1u  [C0603]
CB23  0.1u  [C0603]
CB24  0.1u  [C0603]
CON3  DC5V  [PJ-20POWRJACK\3P]
CON4  BAT1(NC)  [SIP3-2.0mm]
CON5  BAT2(NC)  [HEADER22.54MM]
CP18  47u  [CAP_B]
CP19  47u  [CAP_B]
CP20  47u  [CAP_B]
CP21  47u  [CAP_B]
CX1  0.1u  [C0603]
CX2  30p  [C0603]
CX3  0.1u  [C0603]
CX4  30p  [C0603]
CX5  10n  [C0603]
D1  RB161M  [SOD-123]
LED1  Power  [LED_0603]
LX1  4.7uH  [SMTDR32]
LX2  4.7uH  [SMTDR32]
Q1  IS2301  [SOT-23-GSD]
Q2  IS2301  [SOT-23-GSD]
Q3  2N3906  [SOT23-BEC]
R18  10K  [R0603]
R19  100K  [R0603]
R20  1K  [R0603]
R21  10K  [R0603]
R22  4K7  [R0603]
R23  10K  [R0603]
RX1  680K  [R0603]
RX2  150K  [R0603]
RX3  51K  [R0603]
RX4  240K  [R0603]
RX5  120K  [R0603]
S3  PWR_ON_OFF  [SST-1200]
U2  ZT7104AS  [SOT23-5L]
U3  ZT7104AS  [SOT23-5L]
U4  XC6206P182MR  [SOT-23-GOI]
ZD1  5V6  [DIP2x1PITCH6MM]
sheet TOP
CB1  0.1u  [C0603]
CB2  0.1u  [C0603]
CB3  0.1u  [C0603]
CON1  LCD  [M_DIN_32X2/2.54A]
CON2  HEADER 5X2(NC)  [CON/5X2/2.54/M]
CP1  10u  [CAP_A]
CP2  10u  [CAP_A]
CP3  10u  [CAP_A]
E49  NSP4201(NC)  [TSOP-6]
E50  NSP4201(NC)  [TSOP-6]
E51  NSP4201(NC)  [TSOP-6]
E52  NSP4201(NC)  [TSOP-6]
E53  NSP4201(NC)  [TSOP-6]
E54  NSP4201(NC)  [TSOP-6]
E55  NSP4201(NC)  [TSOP-6]
E56  NSP4201(NC)  [TSOP-6]
E57  NSP4201(NC)  [TSOP-6]
E58  NSP4201(NC)  [TSOP-6]
E59  NSP4201(NC)  [TSOP-6]
E60  NSP4201(NC)  [TSOP-6]
E61  NSP4201(NC)  [TSOP-6]
E62  NSP4201(NC)  [TSOP-6]
S1  SS1n  [3P-1.2mm]
TP1  T POINT R  [1PAD_1.25X1.25MM]
sheet USB_SD
C8  10p(NC)  [C0603]
C9  10p(NC)  [C0603]
CON6  MICRO_USB  [MICRO_USB_AB_LS]
CON7  TF Socket(NC)  [B8502A-13SB-HPA]
CON8  TF Socket  [B8502A-13SB-HPA]
CP22  10u(NC)  [CAP_A]
CP23  10u  [CAP_A]
CX6  NP(NC)  [C0603]
CX7  NP(NC)  [C0603]
E44  NSP4201(NC)  [TSOP-6]
E45  NSP4201(NC)  [TSOP-6]
E46  NSP4201(NC)  [TSOP-6]
E47  NSP4201(NC)  [TSOP-6]
E48  NSP4201(NC)  [TSOP-6]
L9  FB  [L0603]
R35  200K  [R0603]
R36  4R7  [R0603]
R37  4R7  [R0603]
R38  390K  [R0603]
R39  100K(NC)  [R0603]
R40  100K(NC)  [R0603]
R41  33(NC)  [R0603]
R42  0  [R0603]
R43  33  [R0603]
RN2  10KR(NC)  [8P4R_0603]
RN3  10KR  [8P4R_0603]
RN4  10KR  [8P4R_0603]
S4  TF_CD  [3P-1.2mm]
S5  SD2  [3P-1.2mm]
S6  SD3  [3P-1.2mm]
S7  SDCMD  [3P-1.2mm]
S8  SDCLK  [3P-1.2mm]
S9  SD0  [3P-1.2mm]
S10  SD1  [3P-1.2mm]

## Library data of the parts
C22 = CAPACITOR_NON-POL_1
C23 = CAPACITOR_NON-POL_3
C24 = CAPACITOR_NON-POL_15
C25 = CAPACITOR_NON-POL_4
C26 = CAPACITOR_NON-POL_7
C27 = CAPACITOR_NON-POL_13
C28 = CAPACITOR_NON-POL_2
C29 = CAPACITOR_NON-POL_11
C30 = CAPACITOR_NON-POL_9
C31 = CAPACITOR_NON-POL
CB28 = CAPACITOR_NON-POL_8
CB29 = CAPACITOR_NON-POL_12
CB30 = CAPACITOR_NON-POL_10
CB31 = CAPACITOR_NON-POL_6
CB32 = CAPACITOR_NON-POL_14
CP26 = CAPACITOR_NON-POL_5
C10 C16 CP20 CP22 CP24 CP27 = CAPACITOR_POL
CP28 = CAPACITOR_POL_3
CP29 = CAPACITOR_POL_2
C11 CP21 CP23 CP30 = CAPACITOR_POL_1
CP31 = CAPACITOR_POL_4
J1-J3 = CON1
CON5 CON10 JP1 JP2 = HEADER_2
JP3 = HEADER_2_2
JP4 = HEADER_2_1
L9 L10 L12 L16 L18 L22 = INDUCTOR
L8 L11 L15 L19 = INDUCTOR_1
L2 L14 L17 L20 = INDUCTOR_2
L4 L13 L21 = INDUCTOR_3
M1 = MICROPHONE_0_1
M2 = MICROPHONE_0
R6 R23 R39 R45 R53 R62 RS1 = R_6
R2 R28 R63 = R_11
R5 R22 R30 R35 R49 R55 R64 = R_3
R16 R65 RS3 = R_9
R12 R27 R40 R48 R66 RX4 = R_7
R13 R20 R24 R43 R67 = R_8
R3 R68 RS2 = R_10
R11 R26 R69 = R_14
R7 R31 R38 R50 R52 R70 RX1 = R_4
R14 R25 R37 R51 R59 R71 R78 RX5 = R_1
R10 R21 R32 R36 R46 R54 R60 R72 = R
R17 R42 R44 R56 R73 RS6 RX3 = R_2
R8 R33 R41 R47 R57 R74 RX2 = R_5
R15 R34 R75 = R_13
R9 R76 RS5 = R_12
U10 = NAU8501
C6 C12 C21 CB2 CB17 CX6 = CAP_NP_2
C1 C8 C13 C20 CB1 CB24 CB26 = CAP_NP
C2 C14 CB27 CX5 CX7 = CAP_NP_3
CON9 = PJK-634M
CP25 = CAP
C9 C19 CB3 CB19 CB22 CB25 CV1 = CAP_NP_1
E4 = DIODE_ZENER1_3
E1-E3 E5 = DIODE_ZENER1
E6 = DIODE_ZENER1_2
E7 = DIODE_ZENER1_4
E8 = DIODE_ZENER1_1
S1 S4-S10 S12-S15 SW1 = SW-3PAD2
U8 = ISD8101_4
E41-E62 = PJ9293_0
K1-K6 = SW-S_0
R4 R29 = R_16
RN1 = R-PACK4
R1 RS4 = R_15
C3 = CAP_NP_21
C4 CB23 = CAP_NP_9
C5 = CAP_NP_15
C32 = CAP-NP
CB4 = CAP_NP_22
CB5 = CAP_NP_17
CB6 = CAP_NP_11
CB7 = CAP_NP_20
CB8 = CAP_NP_14
CB9 = CAP_NP_10
C17 CB10 CX4 = CAP_NP_4
CB11 = CAP_NP_19
CB12 = CAP_NP_13
CB13 CX1 = CAP_NP_7
CB14 = CAP_NP_16
C7 C18 CB15 = CAP_NP_5
CB16 CX3 = CAP_NP_8
CB18 = CAP_NP_12
CB20 = CAP_NP_18
C15 CB21 CX2 = CAP_NP_6
CP4 = CAP-T_5
CP5 = CAP-T_10
CP6 = CAP-T_3
CP7 = CAP-T_11
CP2 CP8 CP19 = CAP-T_1
CP9 = CAP-T_7
CP10 = CAP-T_12
CP1 CP11 = CAP-T_2
CP12 = CAP-T_8
CP3 CP13 CP18 = CAP-T
CP14 = CAP-T_4
CP15 = CAP-T_9
CP16 = CAP-T_13
CP17 = CAP-T_6
L1 = INDUCTOR_8
L3 = INDUCTOR_4
L5 = INDUCTOR_5
L6 = INDUCTOR_7
L7 = INDUCTOR_6
R77 = RES
S2 = SW3PAD-S
TP1-TP4 = T_POINT_R
U1 = N3290xK3DN_0
X1 = MA306_SM_1
X2 = Crystal_SMD_2
SW2 = S2PH-S
U5 = W55X10_0
U6 = NAND_4-8G_1
U7 = W25Q128BV_1
CON11 = CON20A
CON12 = CONNECTOR_DB9
Q4 = NPN_4
R18 R19 R58 R61 = RESISTOR
RN2-RN6 = 743C083_SM_0
SW3 = SW-S
U9 = ICL-232E_0
CON3 = Power_Jack_0
CON4 = CON3
D1 = DIODE_SCHOTTKY_0
LED1 = LED
LX1 = INDUCTOR_IRON
LX2 = INDUCTOR_IRON_1
Q1 Q2 = MOSFET_P_4
Q3 = PNP_0
S3 = SW_SPDT
U2 U3 = TPS6220xDBV
U4 = XC6206P182MR_4
ZD1 = DIODE_ZENER_0
CON1 = CON40A_0
CON2 = HEADER_5X2
CON6 = MiniUSB_2
CON7 CON8 = TF_Socket

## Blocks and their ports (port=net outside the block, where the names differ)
NAND = schematic SHEET 06, on sheet TOP: SPI0_CS=GPD13, SPI0_DI=GPD14, SPI0_CLK=GPD12, SPI0_DO=GPD15, ND[7:0], nCE1=GPE8, RnB1=GPD5, nCE2=GPE9, RnB2=GPD6, ALE=GPE10, CLE=GPE11, nWR=GPD8, nRE=GPD7, VD33, VS
MODE = schematic SHEET 04, on sheet TOP: VS, ND0, ND7, GPC4, GPC5, ND2, ND4, ND5, GPA2, GPA3, GPA4, GPA7, VD33
PORT = schematic SHEET 08, on sheet TOP: VS, VD33, TCK=GPD0, TDO=GPD3, TMS=GPD1, TDI=GPD2, nTRST=GPD4, nRESET, TX=GPA10, RX=GPA11, VD18
USB_SD = schematic SHEET 05, on sheet TOP: USBDP, USBDM, SD_CD=GPA0, USB_DET, SD_D2=GPE4, VD33, VS, SD_D3=GPE5, SD_CMD=GPE6, SD_CLK=GPE7, SD_D0=GPE2, SD_D1=GPE3, GPD[8:5], GPE[9:8], GPE11, GPB[6:0]
AUDIO = schematic SHEET 09, on sheet TOP: SDIO=GPB14, SCLK=GPB13, MCLK=GPB2, BCLK=GPB3, FS=GPB4, DACIN=GPB5, ADCOUT=GPB6, VD33, VS, ROUT, LOUT
AV = schematic SHEET 07, on sheet TOP: VD33, VS, AMP_EN0=GPE1, HP_DET0=GPE0, AMP_EN1=GPD4, HP_DET1=GPD3, DAC0, LOUT, DAC1, ROUT
POWER = schematic SHEET 03, on sheet TOP: VD33, VD18, VS, RTC18V
N9H20Kx = schematic SHEET 02, on sheet TOP: USBDM, USBDP, TP[4:1], USB_DET, nRESET, GPB[15:0], GPD[15:0], GPE[11:0], GPC[15:0], GPA[7:0], VD18, VS, RTC18V, DAC[1:0], VD33, GPA[11:10], ND[7:0]

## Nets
AUDIO/VDDA: CB29.1 CP28.1 L18.2 U10.31(VDDA)
AUDIO/VDDC: CB30.1 CP29.1 L19.2 U10.13(VDDC)
DVDD33: E55.5(Vp) E56.5(Vp) E57.5(Vp) E58.5(Vp) E59.5(Vp) E60.5(Vp)
POWER/5VIN: C7.1 CP19.1 D1.C Q1.2(S) Q2.2(S) Q3.2(E) R21.1
POWER/VIN: C6.1 CP18.1 CX1.1 CX3.1 Q2.3(D) U2.1(VIN) U3.1(VIN) U4.3(VIN)
VDD18: CB7.1 CB8.1 CB9.1 CB10.1 CP7.1 CP8.1 CP9.1 CP10.1 L2.1 U1.18(VDD18) U1.53(VDD18) U1.83(VDD18) U1.97(VDD18)
VDD33: CB4.1 CB5.1 CB6.1 CP4.1 CP5.1 CP6.1 L1.1 U1.55(VDD33) U1.68(VDD33) U1.89(VDD33) U1.116(VDD33)
VDDB: CB31.1 CP30.1 L20.2 U10.14(VDDB)
VDDP: CB32.1 CP31.1 L21.2 U10.26(VDDSPK)
VSS: C2.2 C3.2 C4.1 C5.2 C32.2(C1B) CB4.2 CB5.2 CB6.2 CB7.2 CB8.2 CB9.2 CB10.2 CP4.2 CP5.2 CP6.2 CP7.2 CP8.2 CP9.2 CP10.2 E1.ANODE R1.1 U1.51(VSS) U1.114(VSS) X2.2(GND) X2.4(GND)
VSSA: CB28.2 CB29.2 CP26.2 CP27.2 CP28.2 R62.1 R68.1 R71.1 R72.1 R73.1 U10.28(VSSA) U10.33(EPAD)
VSSD: CB30.2 CB31.2 CP29.2 CP30.2 R74.1 R76.2 U10.12(VSSD)
VSSP: CB32.2 CP31.2 R63.1 R64.1 R75.1 U10.24(VSSSPK)
ADAVDD33: CP17.1 L8.1 U1.96(ADAC_VDD33)
ADAVSS: C1.2 CP17.2 R16.2 U1.94(ADAC_VSS33)
ADCVDD: CB17.1 CP14.1 L5.1 U1.61(ADC_VDD33)
ADCVSS: CB17.2 CB19.2 CB20.2 CB21.2 CP14.2 R6.1 R10.2 R12.2 R14.2 U1.56(ADC_VSS33)
AUDIO/AUI1: C26.2 JP3.1
AUDIO/AUI2: C27.2 JP3.2
AUDIO/AUO1: C22.2 JP2.1 R63.2
AUDIO/AUO2: C25.2 JP2.2 R64.2
AUDIO/AUXOUT1: C25.1 U10.21(AUXOUT1)
AUDIO/AUXOUT2: C22.1 U10.22(AUXOUT2)
AUDIO/CSB: J1.1 U10.15(CSB/GPIO1)
AUDIO/GPIO2: J2.1 U10.3(LLIN/GPIO2)
AUDIO/GPIO3: J3.1 U10.6(RLIN/GPIO3)
AUDIO/IBCLK: R67.1 U10.8(BCLK)
AUDIO/IMCLK: R69.2 U10.11(MCLK)
AUDIO/ISCLK: R70.1 U10.16(SCLK)
AUDIO/LAUXIN: C27.1 U10.19(LAUXIN)
AUDIO/LHP: C31.1 U10.30(LHP)
AUDIO/LMICN: C23.2 U10.2(LMICN)
AUDIO/LMICP: C24.2 U10.1(LMICP)
AUDIO/LSPKOUT: JP4.2 U10.25(NC)
AUDIO/MICBIAS: CB28.1 CP27.1 R65.2 R66.2 U10.32(MICBIAS)
AUDIO/MODE: R76.1 U10.18(MODE)
AUDIO/RAUXIN: C26.1 U10.20(RAUXIN)
AUDIO/RHP: C30.1 U10.29(RHP)
AUDIO/RMICN: C29.2 U10.5(RMICN)
AUDIO/RMICP: C28.2 U10.4(RMICP)
AUDIO/RSPKOUT: JP4.1 U10.23(NC)
AUDIO/VREF: CP26.1 U10.27(VREF)
AV/AIN: C12.1 CON9.5 CON9.6
AV/SPKVDD: CB27.1 CP25.1 L14.2 R55.1 U8.8(VDD)
DAC0: R51.1 U1.92(ADAC_HPL)
DAC1: R52.1 U1.93(ADAC_HPR)
GPA0: CON2.6 CON8.9(CD) E61.6(CH4) RN4.2 U1.75(GPA0)
GPA1: CON1.3 E49.1(CH1) U1.74(GPA1/SD_nCD)
GPA2: E43.3(CH2) R25.2 U1.73(GPA2/LVMVSYNC)
GPA3: E43.1(CH1) R28.2 U1.72(GPA3/UHL_DP1)
GPA4: E43.4(CH3) R31.2 U1.71(GPA4/UHL_DM1)
GPA5: E61.3(CH2) S1.3(\) U1.70(GPA5/SPI0_nCS1)
GPA6: CON1.4 E49.6(CH4) U1.69(GPA6/SPI1_nCS1)
GPA7: E3.CATHODE R33.1 U1.98(GPA7)
GPA10: U1.117(URTXD/GPA10/SPI1_nCS1) U9.11(T1IN)
GPA11: U1.118(URRXD/GPA11/LVMVSYNC) U9.12(R1OUT)
GPB0: CON1.64 E60.4(CH3) E62.4(CH3) S10.3(\) U1.3(GPB0/UHL_DP1/SD1_D1)
GPB1: CON1.63 E59.3(CH2) S9.3(\) U1.2(GPB1/UHL_DM1/SD1_D0)
GPB2: CON1.62 E60.6(CH4) R69.1 S8.3(\) U1.1(SD1_CLK/I2S_MCLK/PB2)
GPB3: CON1.61 E59.1(CH1) R67.2 S7.3(\) U1.128(GPB3/I2S_BCLK/SD1_CMD)
GPB4: CON1.60 E59.4(CH3) S6.3(\) U1.127(GPB4/I2S_LRCLK/SD1_D3) U10.7(FS)
GPB5: CON1.59 E58.3(CH2) S5.3(\) U1.126(GPB5/I2S_DO/SD1_D2) U10.10(DACIN)
GPB6: CON1.58 E59.6(CH4) S4.3(\) U1.125(GPB6/I2S_DI) U10.9(ADCOUT)
GPB7: CON1.14 E51.4(CH3) U1.124(GPB7/LVD18)
GPB8: CON1.13 E51.3(CH2) U1.123(GPB8/LVD19)
GPB9: CON1.12 E51.6(CH4) U1.122(GPB9/LVD20/SPI1_CLK)
GPB10: CON1.11 E51.1(CH1) U1.121(GPB10/LVD21/SPI1_nCS0)
GPB11: CON1.10 E50.4(CH3) U1.120(GPB11/LVD22/SPI1_DI)
GPB12: CON1.9 E50.3(CH2) U1.119(GPB12/LVD23/SPI1_DO)
GPB13: CON1.54 E58.4(CH3) R70.2 U1.5(ISCK/GPB13)
GPB14: CON1.53 E58.1(CH1) U1.4(ISDA/GPB14/LVMVSYNC) U10.17(SDIO)
GPB15: CON1.8 E50.6(CH4) U1.54(LPCLK/GPB15)
GPC0: CON1.32 E56.6(CH4) U1.48(LVD0/GPC0)
GPC1: CON1.31 E56.1(CH1) U1.47(LVD1/GPC1)
GPC2: CON1.30 E55.4(CH3) U1.46(LVD2/GPC2)
GPC3: CON1.29 E55.3(CH2) U1.45(LVD3/GPC3)
GPC4: CON1.28 E55.6(CH4) R26.2 U1.44(LVD4/GPC4)
GPC5: CON1.27 E55.1(CH1) R27.2 U1.43(LVD5/GPC5)
GPC6: CON1.26 E54.4(CH3) U1.42(LVD6/GPC6)
GPC7: CON1.25 E54.3(CH2) U1.41(LVD7/GPC7)
GPC8: CON1.24 E54.6(CH4) U1.40(LVD8/GPC8)
GPC9: CON1.23 E54.1(CH1) U1.39(LVD9/GPC9)
GPC10: CON1.22 E53.4(CH3) U1.38(LVD10/GPC10)
GPC11: CON1.21 E53.3(CH2) U1.37(LVD11/GPC11)
GPC12: CON1.20 E53.6(CH4) U1.36(LVD12/GPC12)
GPC13: CON1.19 E53.1(CH1) U1.35(LVD13/GPC13)
GPC14: CON1.18 E52.4(CH3) U1.34(LVD14/GPC14)
GPC15: CON1.17 E52.3(CH2) U1.33(LVD15/GPC15)
GPD0: CON1.37 E56.3(CH2) RN6.4 U1.77(TCK/GPD0/SPI1_nCS1/PWM0)
GPD1: RN6.3 U1.78(TMS/GPD1/HUR_Tx/PWM1)
GPD2: RN6.2 U1.79(TDI/GPD2/HUR_Rx/PWM2)
GPD3: R61.2 S14.3(\) U1.80(TDO/GPD3/HUR_CTS/PWM3)
GPD4: E62.1(CH1) RN6.1 S1.1(\) S15.3(\) U1.81(nTRST/GPD4/HUR_RTS/SPI0_nCS1)
GPD5: R48.1 S6.1(\) U1.108(NBUSY0n/GPD5/SD1_D3) U6.7(R/~{B1})
GPD6: R46.1 R50.1 S5.1(\) U1.107(NBUSY1n/GPD6/SD1_D2)
GPD7: S8.1(\) U1.110(NRE/GPD7/SD1_CLK) U6.8(~{RE})
GPD8: S7.1(\) U1.109(NWR/GPD8/SD1_CMD) U6.18(~{WE})
GPD9: CON1.7 E50.1(CH1) U1.52(LVHSYNC/GPD9)
GPD10: CON1.6 E49.4(CH3) U1.50(LVVSYNC/GPD10)
GPD11: CON1.5 E49.3(CH2) U1.49(LVDE/GPD11)
GPD12: CON2.9 U1.6(SPI0_CLK/GPD12) U5.6(CLK) U7.16(CLK)
GPD13: R45.1 U1.7(SPI0_nCS0/GPD13) U5.1(/CS) U7.7(CS)
GPD14: CON2.10 E62.6(CH4) U1.8(SPI0_DI/GPD14) U5.2(DO) U7.8(DO)
GPD15: CON2.8 E61.4(CH3) U1.9(SPI0_DO/GPD15) U5.5(DI) U7.15(DI)
GPE0: CON1.16 E52.6(CH4) S14.1(\) U1.32(LVD16/GPE0)
GPE1: CON1.15 E52.1(CH1) S15.1(\) U1.31(LVD17/GPE1)
GPE2: CON8.7(DAT0) E46.3(CH2) RN4.4 U1.14(SD0_D0/GPE2)
GPE3: CON8.8(DAT1) E46.1(CH1) RN4.3 U1.15(SD0_D1/GPE3)
GPE4: CON8.1(DAT2) E45.3(CH2) RN3.3 U1.10(SD0_D2/GPE4)
GPE5: CON8.2(DAT3) E45.1(CH1) RN3.2 U1.11(SD0_D3/GPE5)
GPE6: CON8.3(CMD) E45.4(CH3) RN3.1 U1.12(SD0_CMD/GPE6)
GPE7: R43.2 U1.13(SD0_CLK/GPE7)
GPE8: R78.1 S10.1(\) U1.115(NCS0n/GPE8/SD1_D1)
GPE9: R49.1 S9.1(\) U1.113(NCS1n/GPE9/SD1_D0)
GPE10: U1.112(NALE/GPE10) U6.17(ALE)
GPE11: S4.1(\) U1.111(NCLE/GPE11) U6.16(CLE)
HPVDD: CP13.1 L4.1 U1.91(ADAC_HPVDD33)
HPVSS: CP13.2 R3.1 U1.90(ADAC_HPVSS33)
LOUT: C31.2 R71.2 S12.3(\)
MODE/Row1: K1.2 K3.2 K5.2 R33.2
MVDD: CB11.1 CB12.1 CB13.1 CB14.1 CB15.1 CP11.1 CP12.1 L3.1 R4.1 U1.20(MVDDQ) U1.22(MVDDQ) U1.84(MVDDQ) U1.88(MVDDQ)
MVSS: CB11.2 CB12.2 CB13.2 CB14.2 CB16.1 CB18.2 CP11.2 CP12.2 R2.1 R5.2 U1.19(MVSSQ) U1.21(MVSSQ) U1.23(MVSSQ) U1.85(MVSS) U1.87(MVSSQ)
N9H20Kx/ADAVREF: C1.1 U1.95(ADAC_VREF)
N9H20Kx/AIN2: CB19.1 R9.2 R10.1 U1.62(ADC_AIN2)
N9H20Kx/AIN3: CB20.1 R11.2 R12.1 U1.63(ADC_AIN3)
N9H20Kx/AIN4: CB21.1 R13.2 R14.1 U1.64(ADC_AIN4)
N9H20Kx/MVREF: CB15.2 CB16.2 CB18.1 R4.2 R5.1 U1.24(MVREF) U1.86(MVREF)
N9H20Kx/nRST: L22.2 U1.76(nRST)
N9H20Kx/USBREXT: R7.2 U1.30(USB_REXT)
N9H20Kx/X11: C4.2 R17.2 U1.16(XIN) X2.1(XIN)
N9H20Kx/X12: C5.1 R17.1 U1.17(XOUT) X2.3(XOUT)
N9H20Kx/X21: C2.1 R8.1 U1.66(RTC_XIN) X1.2
N9H20Kx/X22: C3.1 R8.2 U1.65(RTC_XOUT) X1.1
NAND/NVDD33: CB25.1 CB26.1 CP24.1 L10.2 R44.2 R45.2 R46.2 R47.2 R48.2 SW1.1(\) U5.3(/WP) U5.7(/HOLD) U5.8(VCC) U6.1(VCC) U6.12(VCC) U6.24(VCC) U6.34(VCC) U6.37(VCC) U7.1(HOLD) U7.2(VCC) U7.9(WP)
NAND/PSL: SW1.2(\) U6.39(PSL)
ND0: R24.2 U1.99(ND0) U6.29(I/O0)
ND1: U1.100(ND1) U6.30(I/O1)
ND2: R29.2 U1.101(ND2) U6.31(I/O2)
ND3: U1.102(ND3) U6.32(I/O3)
ND4: R32.2 U1.103(ND4) U6.41(I/O4)
ND5: R34.2 U1.104(ND5) U6.42(I/O5)
ND6: U1.105(ND6) U6.43(I/O6)
ND7: R30.2 U1.106(ND7) U6.44(I/O7)
nRESET: C15.1 CON1.50 CON2.5 CON11.15 E1.CATHODE E2.CATHODE E42.4(CH3) E58.6(CH4) E61.1(CH1) Q4.3(C) R58.2 R59.1 R77.1(R1A) SW3.1
PORT/IVD33: CON11.1 CON11.2 L15.1
PORT/UVD33: C16.1 C17.1 L16.2 U9.16(VDD)
POWER/PWREN: RX3.1 S3.COMMON U2.3(CE)
ROUT: C30.2 R72.2 S13.3(\)
RTC18V: CB24.1 S3.NO U1.67(RTC_VDD) U4.2(VOUT)
SDVDD33: CON7.4(VDD) CON8.4(VDD) CP22.1 CP23.1 R39.1 R40.1 R42.2 RN2.5 RN2.6 RN2.7 RN2.8 RN3.5 RN3.6 RN3.7 RN3.8 RN4.5 RN4.6 RN4.7 RN4.8
SPI_SS1n: CON2.7 S1.2(\)
TP1: CON1.46 E57.4(CH3) U1.60(TP_YP)
TP2: CON1.44 E57.6(CH4) U1.57(TP_YM)
TP3: CON1.41 E57.1(CH1) U1.59(TP_XP)
TP4: CON1.43 E57.3(CH2) U1.58(TP_XM)
USB_CVSS: CON6.5(GND) CON6.6(S1) CON6.7(S2) CON6.8(S3) CON6.9(S4) CX6.2 CX7.2 L9.2
USB_DET: R35.2 R38.2 U1.82(USB_Det)
USB_SD/iSD_CLK: C9.1 CON8.5(CLK) E46.4(CH3) R43.1
USB_SD/iSDCLK: C8.1 CON7.5(CLK) E48.4(CH3) R41.1
USB_SD/SD2_D0: CON7.7(DAT0) E48.3(CH2) RN2.2 S9.2(\)
USB_SD/SD2_D1: CON7.8(DAT1) E48.1(CH1) RN2.1 S10.2(\)
USB_SD/SD2_D2: CON7.1(DAT2) E47.3(CH2) RN2.4 S5.2(\)
USB_SD/SD2_D3: CON7.2(DAT3) E47.1(CH1) RN2.3 S6.2(\)
USB_SD/SDCLK: R41.2 S8.2(\)
USB_SD/SDCMD: CON7.3(CMD) E47.4(CH3) R39.2 S7.2(\)
USB_SD/TF_CD: CON7.9(CD) R40.2 S4.2(\)
USBDM: R36.2 U1.27(USB_DM0)
USBDP: R37.2 U1.28(USB_DP0)
USBVDD18: CP16.1 L7.1 U1.25(USBVDD18)
USBVDD33: CP15.1 L6.1 U1.29(USB_VDD33)
USBVSS: CP15.2 CP16.2 R7.1 R15.1 U1.26(USB_VSS)
VD18: C14.1 CB23.1 CON1.35 CON1.36 CP21.1 CX4.2 L2.2 L7.2 LX2.2 RX4.2 S2.1(\)
VD33: CB1.1 CB2.1 CB3.1 CB22.1 CON1.1 CON1.2 CON2.1 CP1.1 CP2.1 CP3.1 CP20.1 CX2.2 E41.5(Vp) E42.5(Vp) E43.5(Vp) E45.5(Vp) E46.5(Vp) E47.5(Vp) E48.5(Vp) E49.5(Vp) E50.5(Vp) E51.5(Vp) E52.5(Vp) E53.5(Vp) E54.5(Vp) E61.5(Vp) E62.5(Vp) L1.2 L4.2 L5.2 L6.2 L8.2 L10.1 L14.1 L15.2 L16.1 L18.1 L19.1 L20.1 L21.1 LX1.2 R20.1 R42.1 R53.2 R58.1 R59.2 RN1.1 RN1.2 RN1.3 RN1.4 RN5.6 RN5.7 RN5.8 RX1.2 S2.3(\)
VS: C6.2 C7.2 C8.2 C9.2 C13.1 C15.2 C16.2 C17.2 C20.2 C21.2 CB1.2 CB2.2 CB3.2 CB22.2 CB23.2 CB24.2 CB25.2 CB26.2 CB27.2 CON1.39 CON1.40 CON1.47 CON1.48 CON2.3 CON3.1 CON3.2 CON4.1 CON5.1 CON7.6(VSS) CON7.10(GND) CON7.11(GND) CON7.12(GND) CON7.13(GND) CON8.6(VSS) CON8.10(GND) CON8.11(GND) CON8.12(GND) CON8.13(GND) CON11.4 CON11.6 CON11.8 CON11.10 CON11.11 CON11.12 CON11.14 CON11.16 CON11.18 CON11.20 CP1.2 CP2.2 CP3.2 CP18.2 CP19.2 CP20.2 CP21.2 CP22.2 CP23.2 CP24.2 CP25.2 CV1.1 CX1.2 CX3.2 CX5.2 E2.ANODE E3.ANODE E4.ANODE E5.ANODE E6.ANODE E7.ANODE E8.ANODE E41.2(Vn) E42.2(Vn) E43.2(Vn) E44.2(Vn) E45.2(Vn) E46.2(Vn) E47.2(Vn) E48.2(Vn) E49.2(Vn) E50.2(Vn) E51.2(Vn) E52.2(Vn) E53.2(Vn) E54.2(Vn) E55.2(Vn) E56.2(Vn) E57.2(Vn) E58.2(Vn) E59.2(Vn) E60.2(Vn) E61.2(Vn) E62.2(Vn) JP1.1 K2.2 K4.2 K6.2 L9.1 L13.1 L17.1 LED1.2(CATHODE) Q4.2(E) R1.2 R2.2 R3.2 R6.2 R15.2 R16.1 R19.1 R23.2 R38.1 R57.2 R60.2 R73.2 R74.2 R75.2 RN5.5 RS1.1 RS2.1 RS3.1 RS4.1 RS5.1 RS6.1 RX2.1 RX5.1 S3.NC SW1.3(\) SW2.1(\) SW3.4 U2.2(VSS) U3.2(VSS) U4.1(VSS) U5.4(GND) U6.2(VSS) U6.13(VSS) U6.23(VSS) U6.25(VSS) U6.36(VSS) U6.48(VSS) U7.10(GND) U8.3(VSS) U8.9(GPAD) U9.15(GND) ZD1.A
Vsen: CON1.42 E56.4(CH3) TP1.1(TP)
AUDIO/N15508599: C29.1 M2.2 R68.2
AUDIO/N15508603: C28.1 M2.1 R66.1
AUDIO/N15510023: C23.1 M1.2 R62.2
AUDIO/N15510027: C24.1 M1.1 R65.1
AV/N15485471: R56.2 U8.5(INV)
AV/N15485599: R55.2 R57.1 S15.2(\) U8.7(CE)
AV/N15485701: CON9.3 E5.CATHODE L11.2
AV/N15485705: CON9.4 E6.CATHODE L12.2
AV/N15485829: CON10.2 E7.CATHODE U8.2(SPP)
AV/N15485865: C12.2 R56.1
AV/N15486609: C13.2 U8.4(INP) U8.6(VREF)
AV/N15487031: CON10.1 E8.CATHODE U8.1(SPN)
AV/N15487047: L11.1 S12.2(\)
AV/N15492172: CON9.1 CON9.2 L13.2
AV/N15510507: CON9.7 CV1.2 E4.CATHODE R53.1 R54.2
AV/N16785436: R54.1 S14.2(\)
AV/N16794938: C10.1 R51.2
AV/N16795020: L12.1 S13.2(\)
AV/N16795287: C10.2 S12.1(\)
AV/N16797226: C11.1 R52.2
AV/N16797254: C11.2 S13.1(\)
MODE/N15366435: K1.3 K2.4
MODE/N15366459: K3.3 K4.4
MODE/N15366483: K5.3 K6.4
MODE/N15366537: K2.3 R25.1 RN1.5
MODE/N15579410: JP1.2 R24.1
MODE/N15580529: R26.1 RS1.2
MODE/N15583892: R27.1 RS2.2
MODE/N15589228: K6.3 R31.1 RN1.7
MODE/N15590575: R32.1 RS5.2
MODE/N15590655: R34.1 RS6.2
MODE/N15590722: K4.3 R28.1 RN1.6
MODE/N15592121: R30.1 RS4.2
MODE/N16221239: R29.1 RS3.2
N9H20Kx/N15524902: R9.1 TP2.1(TP)
N9H20Kx/N16844062: L3.2 S2.2(\)
N9H20Kx/N16887259: R11.1 TP3.1(TP)
N9H20Kx/N16887322: R13.1 TP4.1(TP)
N9H20Kx/N16895049: C32.1(C1A) L22.1 R77.2(R1B)
NAND/N16780589: R47.1 SW2.2(\) U6.19(NC)
NAND/N16781064: R78.2 U6.9(~{CE1})
NAND/N16781101: R49.2 U6.10(/CE2)
NAND/N16781103: R50.2 U6.6(R/B2)
NAND/N16781226: R44.1 U6.38(VCC)
PORT/N2481187: C14.2 Q4.1(B) R60.1
PORT/N15398583: CON11.7 E41.1(CH1) RN5.3 RN6.6
PORT/N15398627: CON11.13 E42.6(CH4) R61.1
PORT/N15398647: CON11.5 E41.6(CH4) RN5.2 RN6.7
PORT/N15398655: CON11.9 E41.3(CH2) RN5.4 RN6.5
PORT/N15398667: CON11.3 E41.4(CH3) RN5.1 RN6.8
PORT/N15401404: CON12.5 L17.2
PORT/N15401498: CON12.3 U9.13(R1IN)
PORT/N15401502: CON12.2 U9.14(T1OUT)
PORT/N15401902: C20.1 U9.2(V+)
PORT/N15401910: C21.1 U9.6(V-)
PORT/N15401934: C19.1 U9.4(C2+)
PORT/N15401938: C19.2 U9.5(C2-)
PORT/N15401950: C18.2 U9.1(C1+)
PORT/N15401954: C18.1 U9.3(C1-)
POWER/N15483856: CON4.3 CON5.2 Q1.3(D)
POWER/N15484000: Q1.1(G) R18.1 R19.2
POWER/N15484004: CON3.3 D1.A R18.2
POWER/N15504595: CX5.1 RX3.2 U3.3(CE)
POWER/N15504599: CX2.1 RX1.1 RX2.2 U2.4(FB)
POWER/N15504687: CX4.1 RX4.1 RX5.2 U3.4(FB)
POWER/N15504861: LX1.1 U2.5(SW)
POWER/N15504891: LX2.1 U3.5(SW)
POWER/N15505341: LED1.1(ANODE) R20.2
POWER/N15523756: R21.2 R22.2 ZD1.C
POWER/N15523814: Q3.1(B) R22.1
POWER/N15523843: Q2.1(G) Q3.3(C) R23.1
USB_SD/N16777300: CON6.1(VCC) E44.5(Vp) R35.1
USB_SD/N16777429: CON6.2(DM) CX7.1 E44.4(CH3) R36.1
USB_SD/N16778478: CON6.3(DP) CX6.1 E44.6(CH4) R37.1

Not connected (* = marked no-connect by the designer): CON1 33* 34* 38* 45* 49* 51* 52* 55* 56* 57*; CON2 2* 4*; CON4 2*; CON6 4(ID)*; CON11 17* 19*; CON12 1* 4* 6* 7* 8* 9*; E42 1(CH1)* 3(CH2)*; E43 6(CH4)*; E44 1(CH1)* 3(CH2)*; E45 6(CH4)*; E46 6(CH4)*; E47 6(CH4)*; E48 6(CH4)*; E60 1(CH1)* 3(CH2)*; E62 3(CH2)*; K1 1* 4*; K2 1; K3 1* 4*; K4 1; K5 1* 4*; K6 1; RN1 8*; RN3 4*; RN4 1*; SW3 2* 3*; U6 3(NC)* 4(NC)* 5(NC)* 11(NC)* 14(NC)* 15(NC)* 20(NC)* 21(NC)* 22(NC)* 26(NC)* 27(NC)* 28(NC)* 33(NC)* 35(NC)* 40(NC)* 45(NC)* 46(NC)* 47(NC)*; U7 3(NC)* 4(NC)* 5(NC)* 6(NC)* 11(NC)* 12(NC)* 13(NC)* 14(NC)*; U9 7(T2OUT)* 8(R2IN)* 9(R2OUT)* 10(T2IN)*

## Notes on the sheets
sheet 1
- P/N : NK-N9H20
- 3.3V
  GPA1
  VDEN
  HSYNC
  LD23
  LD21
  LD19
  LD17
  LD15
  LD13
  LD11
  LD9
  LD7
  LD5
  LD3
  LD1
  nc
  1.8V
  GPD0
  VSS
  XP
  XM
  nc
  VSS
  nc
  nc
  GPB14
  nc
  nc
  GPB5
  GPB3
  GPB1
- 3.3V
  GPA6
  VSYNC
  PCLK
  LD22
  LD20
  LD18
  LD16
  LD14
  LD12
  LD10
  LD8
  LD6
  LD4
  LD2
  LD0
  nc
  1.8V
  nc
  VSS
  VSEN
  YM
  YP
  VSS
  RESET
  nc
  GPB13
  nc
  GPB6
  GPB4
  GPB2
  GPB0
- LCM
- 3.3V
  VSS
  RESET
  SS1n
  CLK
- nc
  nc
  INT
  MOSI
  MISO
- SPI0 to UART
- SS1n SEL:
  1/2  GPD4
  2/3  GPA5
sheet 2
- HP DET(S14):
  1/2: GPE0
  2/3: GPD3
- For HP detect
- 1
- 1
- Headphone
- PJK-691
- 1
- 8
- 1
- >=15mils
- 7
- 2
- 3
- 6
- L/RIN SEL (S12, S13)
  1/2: Fm N9H20Kx
  2/3: Fm NAV8822
- 4
- 5
- >=15mils
- >=25mils
- 1
- SPK
- AMP EN(S15):
  1/2: GPE1
  2/3: GPD4
sheet 3
- When the USB is not connected, the high level of
  D+/- will be connected to PIN5 through the diode
  inside E44 to affect USB_DET, which should be
  connected to VD33 or 5V.
- TF CD(S4):
  1/2: GPE11
  2/3: GPB6
- USBD
- 1
- 1
- 1
- SD1/SD2
- 1
- 1
- 1
- SD0
- (GPE4)
- (GPE5)
- 1
- (GPE6)
- SD SEL   SD1   SD2
  S4~S10   1/2   2/3
  CLK     GPD7   GPB2
  CMD     GPD8   GPB3
  D0      GPE9   GPB1
  D1      GPE8   GPB0
  D2      GPD6   GPB5
  D3      GPD5   GPB4
  CD      GPE11  GPB6
- R41 should be closed to U1 &
  C8 should be closed to CON7.
- (GPE7)
- (GPE2)
- (GPE3)
- (GPA0)
- R43 should be closed to U1 &
  C9 should be closed to CON8.
sheet 4
- RESET
- JTAG
- UART
sheet 5
- >=10mils
- >=10mils
- MIC_L
- AUXOUT
- NAU8822
- AUXIN
- (EPAD = VSSA)
- SPKOUT
- MIC_R
- >=10mils
- >=25mils
- >=15mils
- >=15mils
- >=15mils
- >=30mils
- (GPB2)
- >=15mils
- (GPB3)
- (GPB4)
- (GPB6)
- (GPB5, NUA882x ONLY)
- (GPB13)
- (GPB14)
- CSB
- GPIO2
- GPIO3
sheet 6
- 1.8V
- --N9H20K11N
- --OTHERS
- 3.3V
sheet 7
- GPC5(RS2)
- GPC4(RS1)
- NAND Page Size
- v
- v
- 2KB
- v
- x
- 4KB
- x
- x
- v
- x
- None (by IBR)
- 8KB
- ND7(RS4)
- NAND Cycle
- v
- 4
- x
- 5
- JP1
- ND0
- SHORT
- Rec. Mode
- OPEN
- Nor. Mode
- ND5(RS6)
- ND4(RS5)
- MEMORY TYPE
- v
- v
- SDRAM
- v
- x
- LPDDR
- JP1
- x
- v
- DDR2
- x
- x
- DDR
- DN
- UP
- LF
- RT
- Home
- ENTER
sheet 8
- DC
  5V
- POWER
  LED
- +
  -
- BAT
- +
  -
- (ZT7104)
- BAT
- 1.8V : 240K/120K
  2.0V : 300K/120K
- ON  OFF
- POWER
sheet 9
- SPI0
- NAND
- GPD12
- GPD14
- GPD15
- GPD13
- 3.3V
  GND
- PSL
- WP
